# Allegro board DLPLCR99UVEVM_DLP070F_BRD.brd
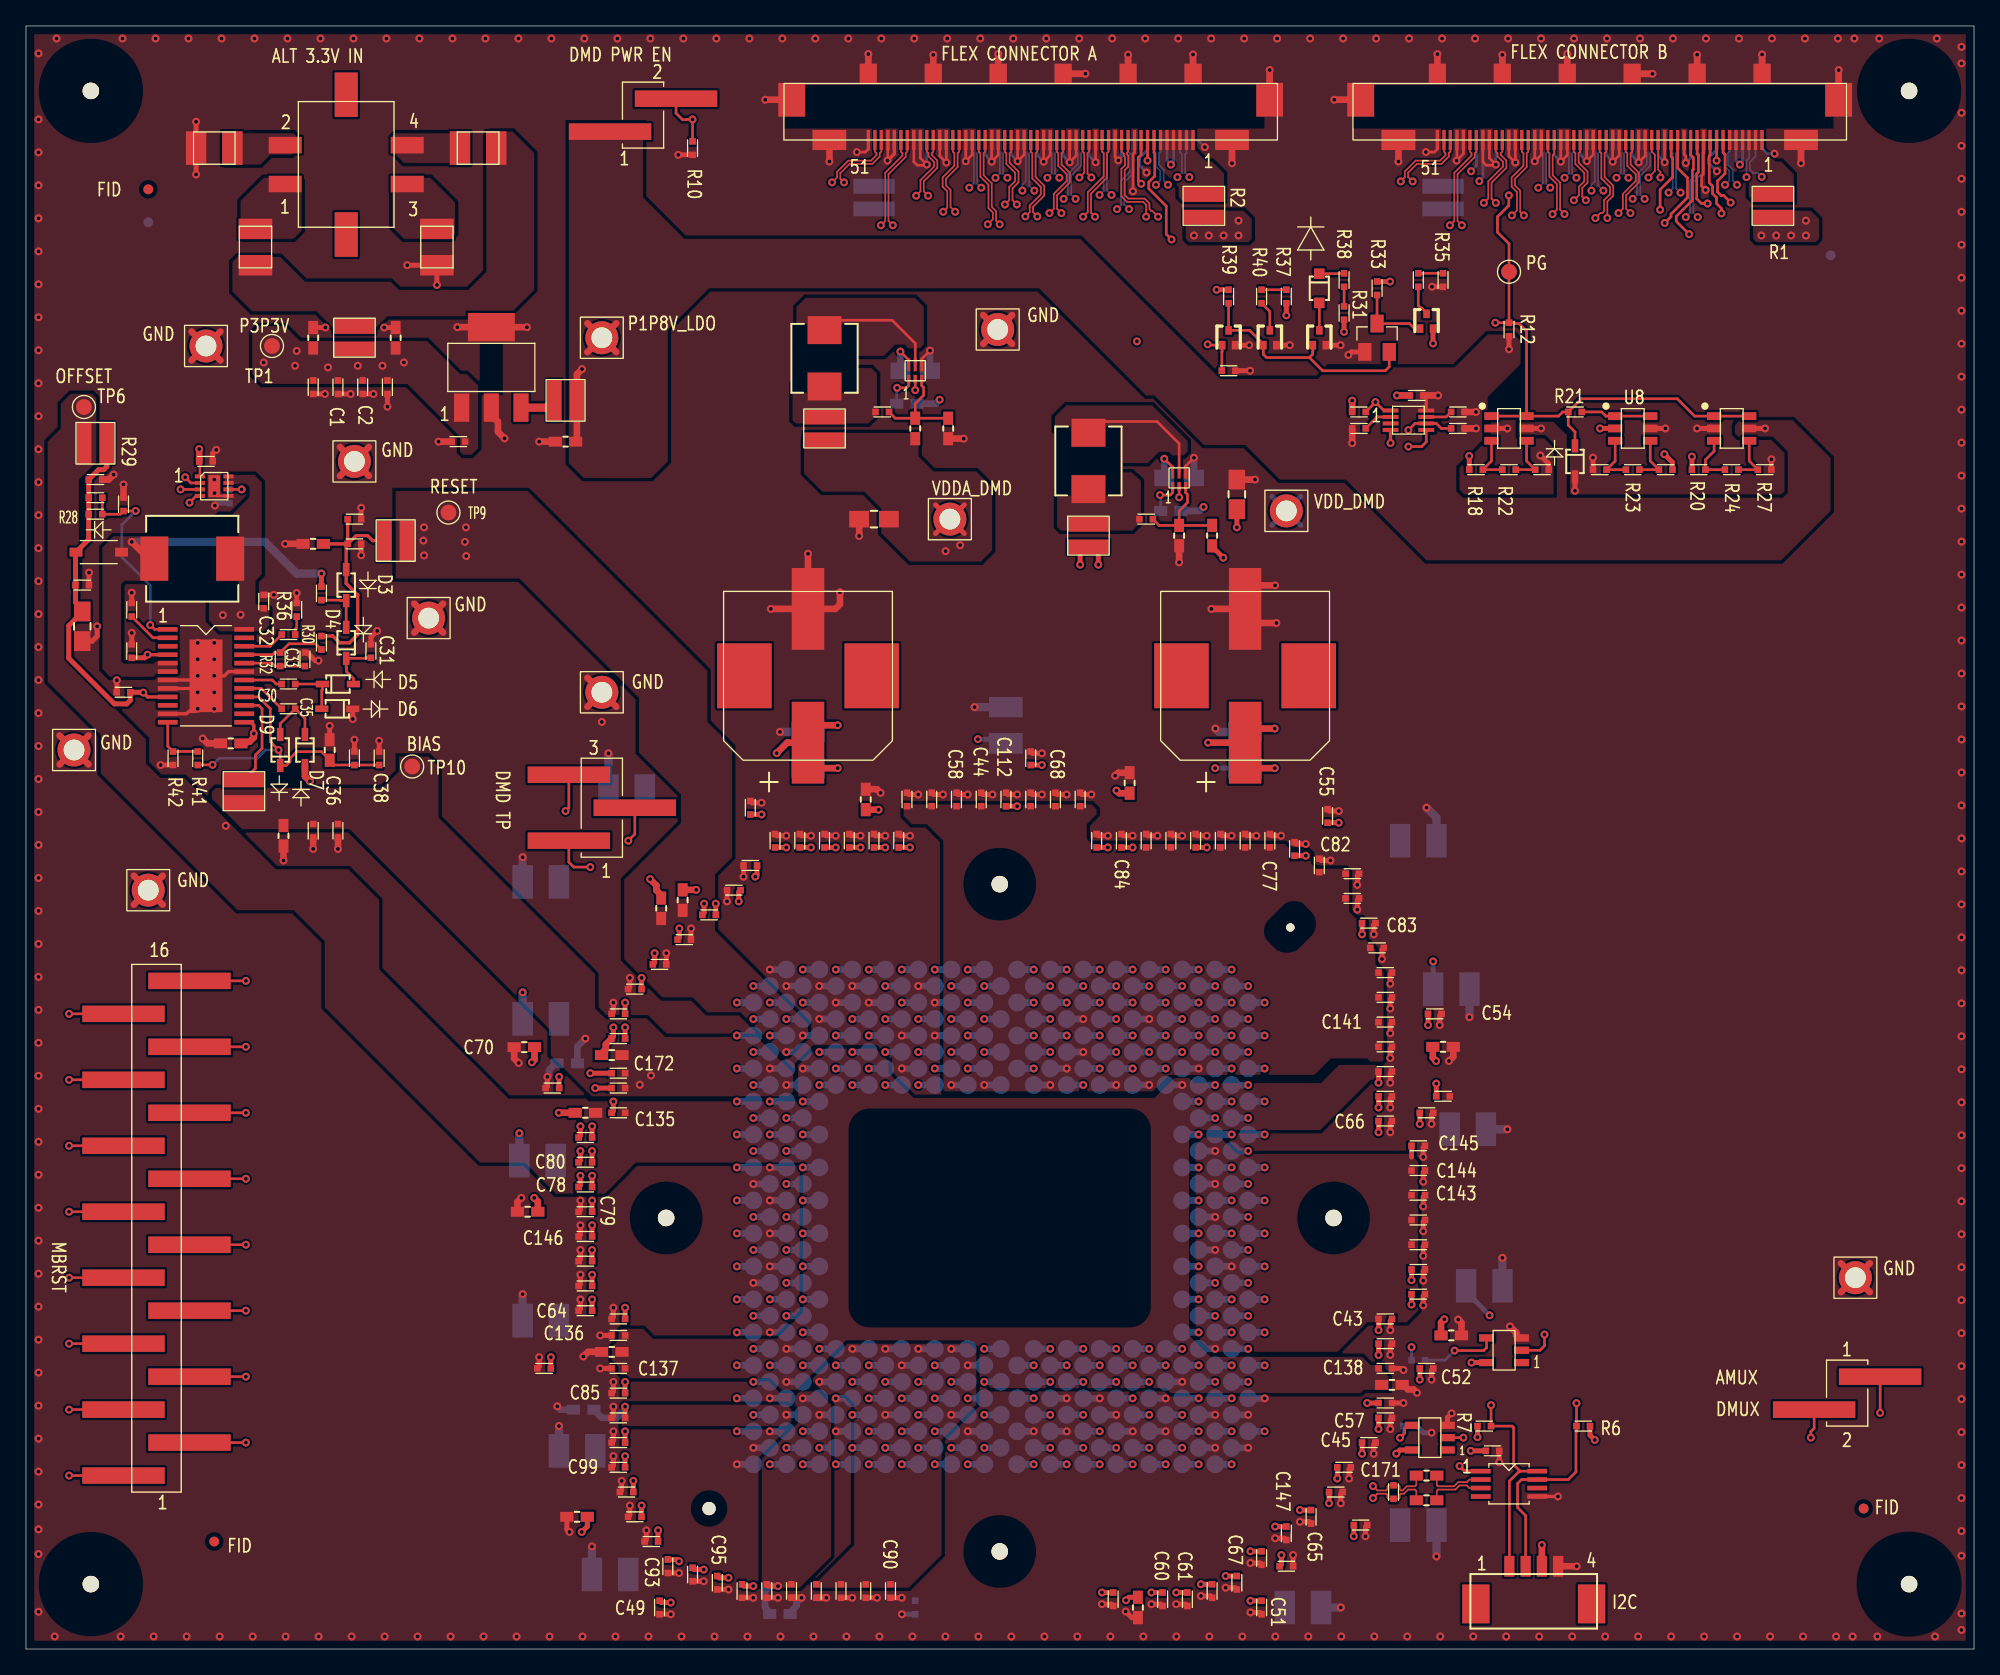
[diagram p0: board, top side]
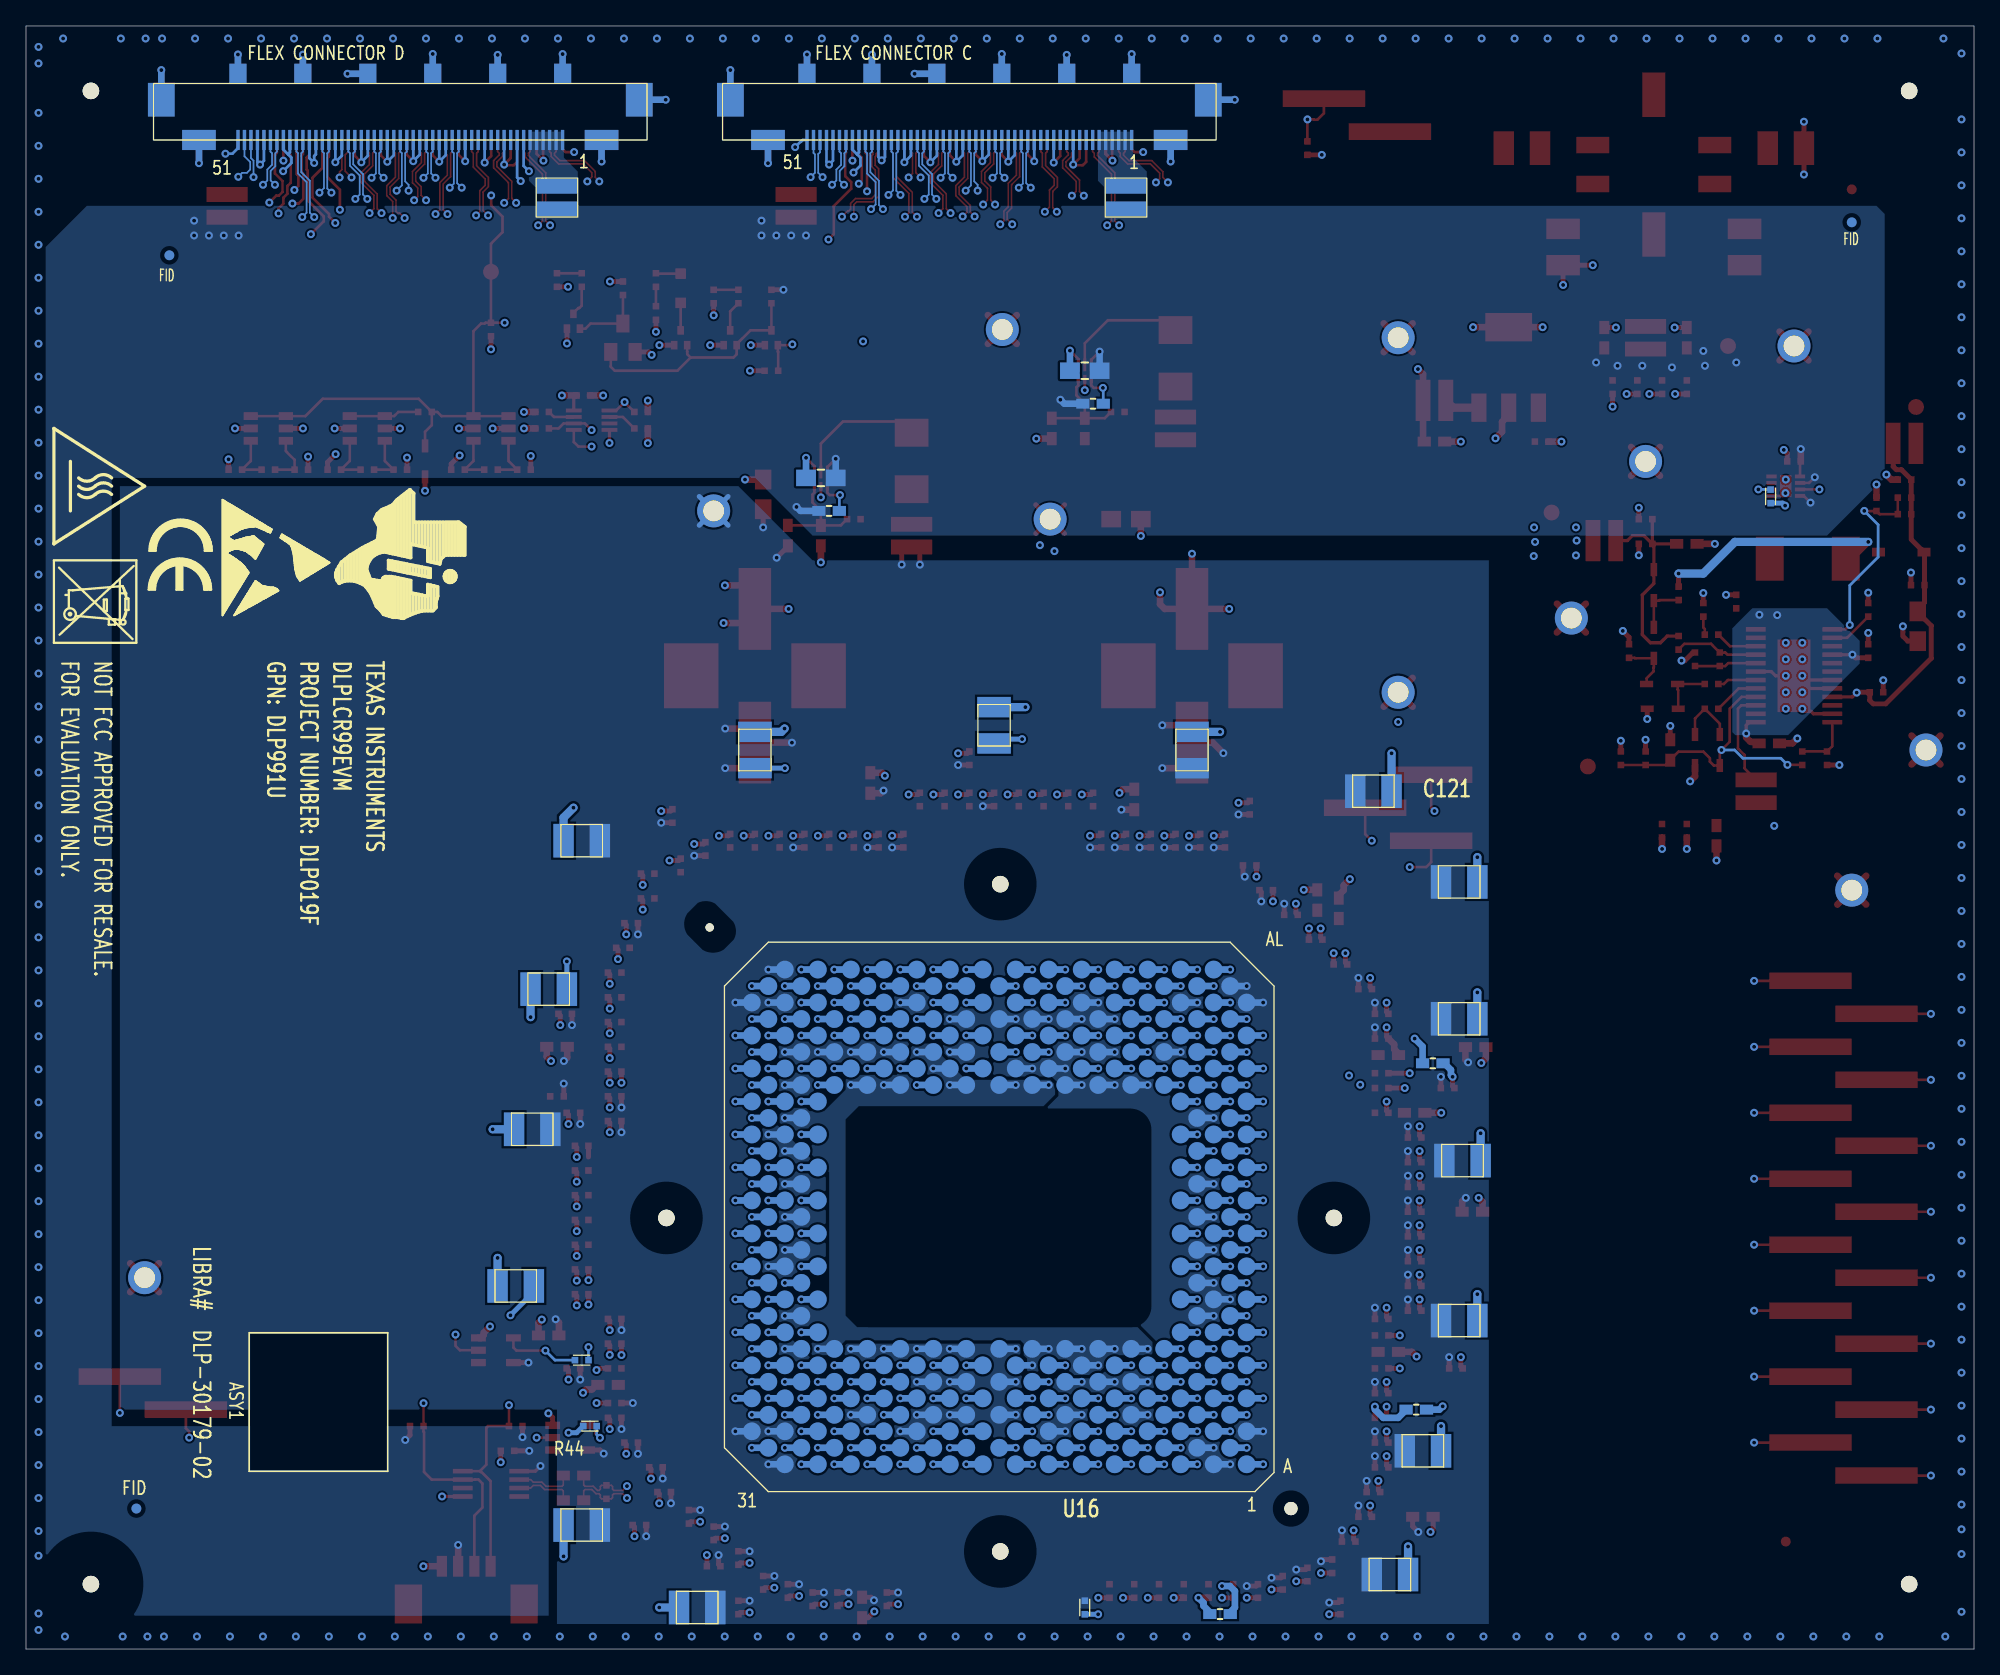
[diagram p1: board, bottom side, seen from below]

Outline 150 x 125 mm; copper layers: TOP, LY2-SIG, LY3-GND, LY4-SIG, LY5-GND, LY6-SIG, LY7-GND, BOTTOM. Coordinates in mm from the lower left corner of the outline.
Outline path: 0,125 150,125 150,0 0,0 0,125

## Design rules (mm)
constraint set DEFAULT: min track width 0.203
net group 100OHM: nets N16806960 N16807032
net group DIFFPAIR1: nets N16806468 N16806470
nets with their own width: min track width 0.381; nets VDD_DMD VDDA_DMD
nets with their own width: min track width 0.508; nets P1P8V_LDO

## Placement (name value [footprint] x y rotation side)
ASY1  -  []  127.52 19.07 180 bottom
C1  1u  [0402]  24.02 97.18 90 top
C2  0.1u  [0402]  25.92 97.18 90 top
C3  10u  [0603]  22.11 100.99 270 top
C4  10u  [0603]  28.46 100.99 270 top
C5  1u  [0402]  22.11 97.18 90 top
C6  0.1u  [0402]  27.83 97.18 90 top
C17  1u  [0402]  13.86 91.46 180 top
C18  4700p  [0402]  15.66 88.77 90 bottom
C19  10u  [0603]  15.76 69.75 0 top
C20  1u  [0402]  8.14 76.86 270 top
C21  0.1u  [0402]  18.3 80.67 270 top
C22  22u  [0805]  4.33 78.76 90 top
C23  1u  [0402]  4.33 81.94 180 top
C24  0.1u  [0402]  7.51 73.68 0 top
C25  47p  [0402]  5.35 88.67 180 top
C26  1u  [0402]  22.75 81.3 90 top
C27  10u  [0603]  22.11 85.11 180 top
C28  1u  [0402]  25.29 85.11 180 top
C29  0.1u  [0402]  25.29 87.02 180 top
C30  1u  [0402]  20.21 74.32 180 top
C31  0.33u  [0402]  26.56 76.86 90 top
C32  470p  [0402]  20.21 78.13 0 top
C33  0.22u  [0402]  21.48 76.22 270 top
C34  8200p  [0402]  8.14 80.03 90 top
C35  1u  [0402]  20.21 72.41 180 top
C36  10u  [0603]  23.38 69.24 90 top
C37  1u  [0402]  25.29 68.6 270 top
C38  0.1u  [0402]  27.19 68.6 270 top
C39  0.1u  [0402]  104.66 50.19 180 top
C40  0.1u  [0402]  97.68 61.62 270 top
C41  0.1u  [0402]  104.66 52.09 180 top
C42  0.1u  [0402]  104.66 18.95 180 top
C43  0.1u  [0402]  104.66 25.42 180 top
C44  0.1u  [0402]  73.55 65.43 270 top
C45  0.1u  [0402]  103.39 15.9 180 top
C46  0.1u  [0402]  68.47 3.2 90 bottom
C47  1u  [0402]  55.77 64.79 270 top
C48  1u  [0402]  45.61 47.01 0 top
C49  1u  [0402]  48.78 3.2 90 top
C50  1u  [0402]  39.89 21.61 0 top
C51  1u  [0402]  95.14 3.2 90 top
C52  1u  [0402]  107.84 21.61 180 top
C53  1u  [0402]  102.76 9.55 180 top
C54  1u  [0402]  108.47 48.92 180 top
C55  1u  [0402]  100.22 64.16 270 top
C56  1u  [0402]  77.36 68.6 270 top
C57  0.1u  [0402]  104.66 17.8 180 top
C58  0.1u  [0402]  71.64 65.43 270 top
C59  0.1u  [0402]  83.71 3.83 90 top
C60  0.1u  [0402]  87.52 3.83 90 top
C61  0.1u  [0402]  89.42 3.83 90 top
C62  0.1u  [0402]  95.14 7.01 90 top
C63  0.1u  [0402]  107.2 33.04 180 top
C64  0.1u  [0402]  43.07 26.06 0 top
C65  0.1u  [0402]  98.95 10.18 90 top
C66  0.1u  [0402]  104.66 40.66 180 top
C67  0.1u  [0402]  93.23 5.1 90 top
C68  0.1u  [0402]  79.26 65.43 270 top
C69  10u  [0603]  64.66 65.43 270 top
C70  10u  [0603]  38.37 46.35 0 top
C71  10u  [0603]  38.62 33.68 0 top
C72  10u  [0603]  42.43 10.18 0 top
C73  10u  [0603]  85.61 3.2 90 top
C74  10u  [0603]  109.74 24.15 180 top
C75  10u  [0603]  109.11 46.38 180 top
C76  10u  [0603]  84.98 66.7 270 top
C77  0.1u  [0402]  95.77 62.25 270 top
C78  0.1u  [0402]  43.07 35.58 0 top
C79  0.1u  [0402]  43.07 33.68 0 top
C80  0.1u  [0402]  43.07 37.49 0 top
C81  0.1u  [0402]  55.13 4.47 90 top
C82  0.1u  [0402]  99.58 60.35 270 top
C83  0.1u  [0402]  103.39 55.9 180 top
C84  0.1u  [0402]  84.34 62.25 270 top
C85  0.1u  [0402]  45.61 19.71 0 top
C86  100u  [1210]  44.97 5.74 0 bottom
C87  100u  [1210]  111.01 40.03 180 bottom
C88  100u  [1210]  39.39 37.62 0 bottom
C89  100u  [1210]  60.21 69.24 270 bottom
C90  0.1u  [0402]  66.56 4.47 90 top
C91  470u  [CAP2-146CTI-1213_VISHAY]  93.87 74.95 270 top
C92  470u  [CAP2-146CTI-1213_VISHAY]  60.21 74.95 270 top
C93  0.1u  [0402]  49.42 6.37 90 top
C94  0.1u  [0402]  62.75 4.47 90 top
C95  0.1u  [0402]  53.23 5.1 90 top
C96  0.1u  [0402]  102.12 57.81 180 top
C97  0.1u  [0402]  107.2 29.23 180 top
C98  0.1u  [0402]  107.2 27.33 180 top
C99  0.1u  [0402]  45.61 13.99 0 top
C100  0.1u  [0402]  43.07 29.87 0 top
C101  0.1u  [0402]  43.07 27.96 0 top
C102  0.1u  [0402]  61.48 62.25 270 top
C103  0.1u  [0402]  63.39 62.25 270 top
C104  0.1u  [0402]  48.15 8.28 0 top
C105  0.1u  [0402]  46.88 10.18 0 top
C106  0.1u  [0402]  69.74 65.43 270 top
C107  0.1u  [0402]  59.58 62.25 270 top
C108  0.1u  [0402]  67.83 65.43 270 top
C109  0.1u  [0402]  67.2 62.25 270 top
C110  0.1u  [0402]  65.29 62.25 270 top
C111  0.1u  [0402]  55.77 60.35 0 top
C112  0.1u  [0402]  75.45 65.43 270 top
C113  100u  [1210]  93.87 69.24 270 bottom
C114  100u  [1210]  107.2 62.25 180 bottom
C115  100u  [1210]  109.74 50.82 180 bottom
C116  100u  [1210]  107.2 9.55 180 bottom
C117  100u  [1210]  98.31 3.2 180 bottom
C118  100u  [1210]  39.64 48.54 0 bottom
C119  100u  [1210]  42.43 15.26 0 bottom
C120  100u  [1210]  39.64 59.08 0 bottom
C121  100u  [1210]  46.24 66.06 0 bottom
C122  100u  [1210]  39.64 25.3 0 bottom
C123  100u  [1210]  75.45 71.14 270 bottom
C124  100u  [1210]  112.28 27.96 180 bottom
C125  0.1u  [0402]  107.2 31.14 180 top
C126  0.1u  [0402]  52.59 56.54 0 top
C127  0.1u  [0402]  54.5 58.44 0 top
C128  0.1u  [0402]  60.85 4.47 90 top
C129  0.1u  [0402]  91.33 4.47 90 top
C130  0.1u  [0402]  104.66 42.57 180 top
C131  0.1u  [0402]  40.53 43.2 0 top
C132  0.1u  [0402]  45.61 48.92 0 top
C133  0.1u  [0402]  43.07 39.39 0 top
C134  0.1u  [0402]  46.88 50.82 0 top
C135  0.1u  [0402]  45.61 41.3 0 top
C136  0.1u  [0402]  45.61 24.15 0 top
C137  0.1u  [0402]  45.61 21.61 0 top
C138  0.1u  [0402]  104.66 21.61 180 top
C139  0.1u  [0402]  104.66 44.47 180 top
C140  0.1u  [0402]  86.25 62.25 270 top
C141  0.1u  [0402]  104.66 48.28 180 top
C142  0.1u  [0402]  81.17 65.43 270 top
C143  0.1u  [0402]  107.2 34.95 180 top
C144  0.1u  [0402]  107.2 36.85 180 top
C145  0.1u  [0402]  107.2 38.76 180 top
C146  0.1u  [0402]  43.07 31.77 0 top
C147  0.1u  [0402]  97.04 8.91 90 top
C148  0.1u  [0402]  104.66 23.52 180 top
C149  0.1u  [0402]  64.66 4.47 90 top
C150  0.1u  [0402]  45.61 25.42 0 top
C151  0.1u  [0402]  100.85 12.09 180 top
C152  0.1u  [0402]  107.84 41.3 180 top
C153  0.1u  [0402]  57.67 62.25 270 top
C154  0.1u  [0402]  51.32 5.74 90 top
C155  0.1u  [0402]  102.12 59.71 180 top
C156  0.1u  [0402]  97.04 6.37 180 top
C157  0.1u  [0402]  45.61 15.9 0 top
C158  0.1u  [0402]  77.36 65.43 270 top
C159  0.1u  [0402]  104.66 46.38 180 top
C160  0.1u  [0402]  57.04 4.47 90 top
C161  0.1u  [0402]  58.94 4.47 90 top
C162  0.1u  [0402]  50.69 54.63 0 top
C163  0.1u  [0402]  48.78 52.73 0 top
C164  0.1u  [0402]  46.24 12.09 0 top
C165  0.1u  [0402]  91.96 62.25 270 top
C166  0.1u  [0402]  82.44 62.25 270 top
C167  0.1u  [0402]  90.06 62.25 270 top
C168  0.1u  [0402]  104.03 54 180 top
C169  0.1u  [0402]  93.87 62.25 270 top
C170  0.1u  [0402]  88.15 62.25 270 top
C171  0.1u  [0402]  101.49 13.99 180 top
C172  0.1u  [0402]  45.61 44.35 0 top
C173  0.1u  [0402]  45.61 43.2 0 top
C174  0.1u  [0402]  45.61 17.8 0 top
C175  0.1u  [0402]  112.92 15.26 180 top
C176  180p  [0402]  105.3 12.09 90 top
C177  2.2u  [0402]  5.35 90.07 180 top
C179  0.1u  [0402]  107.08 96.54 0 top
C181  10u  [0603]  41.55 92.99 0 top
C182  10u  [0603]  43.07 41.3 0 top
C183  10u  [0603]  45.1 22.88 0 top
C184  10u  [0603]  105.17 20.34 180 top
C185  10u  [0603]  48.91 57.05 270 top
C186  10u  [0603]  50.56 57.68 270 top
C187  10u  [0603]  58.06 2.69 180 bottom
C188  10u  [0603]  45.1 45.74 0 top
C189  10u  [0603]  41.67 45.11 0 bottom
C190  10u  [0603]  42.94 18.44 0 bottom
C191  10u  [0603]  19.83 62.64 270 top
C192  1u  [0402]  24.02 63.02 90 top
C193  0.1u  [0402]  22.11 63.02 90 top
C194  120 pF  [0402]  86.25 87.02 180 top
C195  4.7 uF  [0805]  88.79 90.19 180 bottom
C196  33u  [0805]  93.23 88.92 270 top
C197  4.7 uF  [0805]  68.47 98.45 180 bottom
C198  120 pF  [0402]  65.93 95.27 180 top
C199  33u  [0805]  65.29 87.02 0 top
C200  0.1u  [0402]  109.11 42.57 180 top
C201  1u  [0402]  33.29 92.99 0 top
D1  PMEG3010  [SOD323-REV_MCC]  119.27 91.46 270 top
D2  CDBW0540  [SOD-123-STP-REV_ST]  5.6 84.48 180 top
D3  PMEG3010  [SOD323-REV_MCC]  24.65 81.94 90 top
D4  PMEG3010  [SOD323-REV_MCC]  24.65 77.49 90 top
D5  PMEG3010  [SOD323-REV_MCC]  24.02 74.32 0 top
D6  PMEG3010  [SOD323-REV_MCC]  23.97 72.41 180 top
D7  PMEG3010  [SOD323-REV_MCC]  21.48 69.24 270 top
D8  3.3V  [DIO-SOD323F_FC]  99.58 104.8 270 top
D9  PMEG3010  [SOD323-REV_MCC]  19.57 69.24 90 top
FB1  FB  [1210]  34.81 115.59 180 top
FB2  FB  [1210]  17.67 107.97 90 top
FB3  FB  [1210]  31.64 107.97 90 top
FB4  FB  [1210]  14.49 115.59 0 top
FID  -  [unnamed#2]  141.49 10.82 0 top
FID#2  -  [unnamed#2]  9.41 112.42 0 top
FID#3  -  [unnamed#2]  14.49 8.28 0 top
FID#4  -  [unnamed#2]  141.49 10.82 180 bottom
FID#5  -  [unnamed#2]  9.41 109.88 180 bottom
FID#6  -  [unnamed#2]  138.95 107.34 180 bottom
J1  FI-RE51S-HF-R1500  [CONN51-FI-R_JAE]  77.36 118.77 180 top
J2  FI-RE51S-HF-R1500  [CONN51-FI-R_JAE]  121.17 118.77 180 top
J3  FI-RE51S-HF-R1500  [CONN51-FI-R_JAE]  77.36 118.77 0 bottom
J4  FI-RE51S-HF-R1500  [CONN51-FI-R_JAE]  121.17 118.77 0 bottom
J5  0532610471  [CONN4-53261-A_MOLEX]  116.09 6.37 0 top
J6  GBC02SABN-M30  [CONN2-GBC02SABN-M30_SUL]  47.51 118.13 0 top
J7  Molex 43045-0420  [CONN4-43045-0418_MLX]  24.65 114.32 90 top
J8  GBC02SABN-M30  [CONN2-GBC02SABN-M30_SUL]  140.22 19.71 180 top
J9  GBC16SABN-M30  [CONN16-GBC16SABN-M30_SUL]  10.05 32.41 0 top
J10  GBC03SABN-M30  [CONN3-GBC03SABN-M30_SUL]  44.34 64.79 0 top
L2  2.2uH  [IND_SRP7028C]  12.8 83.97 180 top
L3  470 nH  [IND_SPM5030VT]  81.8 91.5 270 top
L4  470 nH  [IND_SPM5030VT]  61.48 99.41 270 top
NOREF  -  []  52.59 10.82 0 top
NOREF#2  -  [unnamed#3]  100.68 33.2 157.5 top
NOREF#3  -  []  -16.9 -14.58 180 top
NOREF#4  -  []  85.97 26.41 0 top
NOREF#5  -  [unnamed#3]  49.29 33.2 157.5 top
NOREF#6  -  [unnamed#3]  74.97 58.91 157.5 top
NOREF#7  -  [unnamed#3]  5 120 0 top
NOREF#8  -  []  213.49 74.66 0 top
NOREF#9  -  []  0 0 0 top
NOREF#10  -  []  0.5 -65.46 0 top
NOREF#11  -  []  84.97 25.41 0 top
NOREF#12  -  []  52.59 10.82 0 top
NOREF#13  -  [unnamed#3]  144.99 120 0 top
NOREF#14  -  [unnamed#3]  5 5 0 top
NOREF#15  -  []  0 125 0 top
NOREF#16  -  []  63.97 39.99 0 top
NOREF#17  -  []  0 0 0 top
NOREF#18  -  []  160.9 137.82 180 top
NOREF#19  -  [unnamed#3]  74.97 7.52 157.5 top
NOREF#20  -  []  9.25 87.27 0 top
NOREF#21  -  []  58.93 96.76 0 top
NOREF#22  -  []  9.25 80.67 90 top
NOREF#23  -  [unnamed#3]  97.36 55.57 135 top
NOREF#24  -  []  58.78 12.05 0 top
NOREF#25  -  [unnamed#3]  52.59 10.82 157.5 top
NOREF#26  -  []  -16.9 137.82 180 top
NOREF#27  -  []  79.25 88.85 90 top
NOREF#28  -  []  150 0 90 top
NOREF#29  -  []  150 0 0 top
NOREF#30  -  []  79.25 88.85 0 top
NOREF#31  -  []  58.93 96.76 90 top
NOREF#32  -  []  0 125 0 top
NOREF#33  -  [unnamed#3]  144.99 5 0 top
NOREF#34  -  []  84.97 40.99 0 top
NOREF#35  -  []  140.22 87.65 270 bottom
NOREF#36  -  []  131.33 83.84 270 bottom
NOREF#37  -  []  147.84 83.84 270 bottom
NOREF#38  -  []  121.17 83.84 270 bottom
NOREF#39  -  []  147.84 94 270 bottom
R1  10m  [1206-WIDE-LTR18_ROHM]  134.51 111.15 270 top
R2  10m  [1206-WIDE-LTR18_ROHM]  90.69 111.15 270 top
R3  10m  [1206-WIDE-LTR18_ROHM]  65.29 111.78 270 bottom
R4  10m  [1206-WIDE-LTR18_ROHM]  109.11 111.78 270 bottom
R6  2.2k  [0402]  119.9 17.17 0 top
R7  2.2k  [0402]  112.28 17.17 180 top
R9  10m  [1206-WIDE-LTR18_ROHM]  25.29 100.99 270 top
R10  10k  [0402]  51.32 115.59 90 top
R12  2.2k  [0402]  114.19 101.62 270 top
R18  1.8MEG  [0402]  111.65 90.83 180 top
R19  2.7MEG  [0402]  121.17 90.83 180 top
R20  3.3MEG  [0402]  128.79 90.83 180 top
R21  9.1k  [0402]  119.27 95.27 180 top
R22  6.2k  [0402]  114.19 90.83 180 top
R23  4.53k  [0402]  123.71 90.83 180 top
R24  3k  [0402]  131.33 90.83 180 top
R25  71.5k  [0402]  116.73 90.83 180 top
R26  76.8k  [0402]  126.25 90.83 180 top
R27  73.2k  [0402]  133.87 90.83 180 top
R28  499k  [0402]  5.35 87.4 180 top
R29  63.4k  [0402]  7.51 88.16 270 top
R30  576k  [0402]  22.75 77.49 90 top
R31  12  [0402]  101.49 102.89 270 top
R32  49.9k  [0402]  19.57 76.22 90 top
R33  2.2k  [0402]  104.03 104.8 90 top
R34  12  [0402]  107.2 105.43 270 top
R35  12  [0402]  109.11 105.43 90 top
R36  56.0K  [0402]  20.84 80.03 90 top
R37  12  [0402]  97.04 104.16 270 top
R38  12  [0402]  101.49 105.43 270 top
R39  1k  [0402]  92.6 104.16 90 top
R40  12  [0402]  95.14 104.16 90 top
R41  649k  [0402]  13.22 68.6 270 top
R42  47k  [0402]  11.32 68.6 90 top
R43  4.7k  [0402]  92.6 98.45 180 top
R44  10k  [0402]  106.57 17.17 180 bottom
R45  0  [0402]  107.2 22.25 0 bottom
R46  51  [0603]  107.84 13.36 0 top
R47  51  [0603]  107.84 11.45 0 top
R48  10m  [1206-WIDE-LTR18_ROHM]  5.35 92.86 180 top
R49  10m  [1206-WIDE-LTR18_ROHM]  28.46 85.37 0 top
R50  10m  [1206-WIDE-LTR18_ROHM]  16.78 66.06 90 top
R53  10k  [0402]  102.63 94 180 top
R54  10k  [0402]  110.25 95.27 0 top
R55  10m  [1206-WIDE-LTR18_ROHM]  41.55 96.16 0 top
R56  10k  [0402]  110.25 94 0 top
R57  10k  [0402]  102.63 95.27 0 top
R58  330k  [0603]  91.33 85.75 270 top
R59  100k  [0603]  88.79 85.75 90 top
R60  100k  [0603]  88.15 87.65 0 bottom
R61  10m  [1206-WIDE-LTR18_ROHM]  81.8 85.75 270 top
R62  10m  [1206-WIDE-LTR18_ROHM]  61.48 94 270 top
R63  100k  [0603]  67.83 95.91 0 bottom
R64  330k  [0603]  68.47 94 270 top
R65  100k  [0603]  71.01 94 90 top
TP1  Testpoint  [TP-48RD]  18.94 100.35 0 top
TP2  GND Testpoint  [TP-5006-GND_KEY]  13.86 100.35 0 top
TP4  GND Testpoint  [TP-5006-GND_KEY]  74.82 101.62 0 top
TP5  Testpoint  [TP-48RD]  114.19 106.07 0 top
TP6  Testpoint  [TP-48RD]  4.46 95.66 0 top
TP7  GND Testpoint  [TP-5006-GND_KEY]  3.7 69.24 0 top
TP8  GND Testpoint  [TP-5006-GND_KEY]  25.29 91.46 0 top
TP9  Testpoint  [TP-48RD]  32.53 87.53 0 top
TP10  Testpoint  [TP-48RD]  29.73 67.97 0 top
TP11  GND Testpoint  [TP-5006-GND_KEY]  31 79.4 0 top
TP12  GND Testpoint  [TP-5006-GND_KEY]  140.86 28.6 0 top
TP13  GND Testpoint  [TP-5006-GND_KEY]  9.41 58.44 0 top
TP14  GND Testpoint  [TP-5006-GND_KEY]  44.34 73.68 0 top
TP15  GND Testpoint  [TP-5006-GND_KEY]  97.04 87.65 0 top
TP16  GND Testpoint  [TP-5006-GND_KEY]  71.14 87.02 0 top
TP17  GND Testpoint  [TP-5006-GND_KEY]  44.34 100.99 0 top
U6  TPS22975  [SOIC8-DSG_TI]  14.49 89.56 0 top
U7  TPS3700  [SOIC6-DDC_TI]  114.19 94 0 top
U8  TPS3700  [SOIC6-DDC_TI]  123.71 94 0 top
U9  TPS3700  [SOIC6-DDC_TI]  131.33 94 0 top
U10  TPS65150  [SOIC24-PWP_TI_A]  13.86 74.95 270 top
U11  SI1012X  [SOT-490-SC89-3_FC]  107.84 102.26 0 top
U12  SI1012X  [SOT-490-SC89-3_FC]  92.6 100.99 0 top
U13  SI1012X  [SOT-490-SC89-3_FC]  95.77 100.99 0 top
U14  SI1012X  [SOT-490-SC89-3_FC]  99.58 100.99 0 top
U15  BSS84  [SOT23-3_FC]  104.03 100.99 180 top
U16  2515700 (Interposer)  [DMD-98-DC4K-TRP-FLRA_TI]  56 14.23 0 bottom
U17  ADT7461  [SOIC8-DGK_TI]  114.19 12.72 270 top
U18  SN74AUC1G74  [SOIC8-DCU_TI]  106.44 94.64 270 top
U19  TLV117118DCYR  [SOT223AVX]  35.83 98.7 0 top
U22  SN74LVC1G17  [SOIC5-SOT-23_DBV-TI]  113.81 23.01 90 top
U23  SN74LVC1G17  [SOIC5-SOT-23_DBV-TI]  108.09 16.28 90 top
U24  TPS62827DMQ  [SOIC6-VSON-HR-DMQ_TI]  88.79 90.19 90 top
U25  TPS62827DMQ  [SOIC6-VSON-HR-DMQ_TI]  68.47 98.45 90 top

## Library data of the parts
C1-C6 C17-C85 C90 C93-C112 C125-C177 C179 C181-C201 = C
C86-C89 C113-C124 = C: Tolerance: TOL
C91 C92 = CAPACITOR_POL
D1-D7 D9 = DIODE_SCHOTTKY_dsize
D8 = DIODE ZENER
FB1-FB4 = Ferrite Bead_1: Tolerance: TOL
J1-J4 = FI-RE51S-VF-R1300
J5 = Conn_4
J6 J8 = 2x1 Header
J7 = Molex 43045-0418_0
J9 = 16x1 Header
J10 = 3x1 Header
L2-L4 = L
R1-R4 R6 R7 R9 R10 R12 R18-R50 R53-R65 = R
TP1 TP2 TP4-TP17 = Testpoint
U6 = TPS22967_4
U7-U9 = TPS3700
U10 = TPS65150_2
U11-U14 = FDV303N
U15 = BSS84
U16 = DLP990U_DMD_SOCKET
U17 = TMP411
U18 = SN74AUC1G74
U19 = TLV117118DCYR
U22 U23 = SN74LVC1G06
U24 U25 = TPS62827DMQ

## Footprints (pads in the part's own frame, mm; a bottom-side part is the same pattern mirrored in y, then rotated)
0402
  rect 0.508x0.508 smd: 1(-0.521,0) 2(0.521,0)
0603
  rect 1.016x0.762 smd: 1(-0.787,0) 2(0.787,0)
0805
  rect 1.524x1.27 smd: 1(-1.143,0) 2(1.143,0)
1206-WIDE-LTR18_ROHM
  rect 1.143x3.175 smd: 1(-0.875,0) 2(0.875,0)
1210
  rect 1.575x2.591 smd: 1(-1.397,0) 2(1.397,0)
CAP2-146CTI-1213_VISHAY
  rect 5x4.2 smd: (0,4.9) (0,-4.9)
  rect 6.3x2.5 smd: 1(5.15,0) 2(-5.15,0)
CONN2-GBC02SABN-M30_SUL
  rect 6.35x1.27 smd: 1(-2.54,-1.27) 2(2.54,1.27)
CONN3-GBC03SABN-M30_SUL
  rect 6.35x1.27 smd: 1(-2.54,-2.54) 2(2.54,0) 3(-2.54,2.54)
CONN4-43045-0418_MLX
  rect 3.429x1.778 smd: (-5.385,0) (5.385,0)
  rect 1.27x2.54 smd: 1(-1.499,4.699) 2(1.499,4.699) 3(-1.499,-4.699) 4(1.499,-4.699)
CONN4-53261-A_MOLEX
  rect 2.108x2.997 smd: (-4.455,-2.9) (4.455,-2.9)
  rect 0.787x1.6 smd: 1(-1.875,0) 2(-0.625,0) 3(0.625,0) 4(1.875,0)
CONN16-GBC16SABN-M30_SUL
  rect 6.35x1.27 smd: 1(-2.54,-19.05) 2(2.54,-16.51) 3(-2.54,-13.97) 4(2.54,-11.43) 5(-2.54,-8.89) 6(2.54,-6.35) 7(-2.54,-3.81) 8(2.54,-1.27) 9(-2.54,1.27) 10(2.54,3.81) 11(-2.54,6.35) 12(2.54,8.89) 13(-2.54,11.43) 14(2.54,13.97) 15(-2.54,16.51) 16(2.54,19.05)
CONN51-FI-R_JAE
  rect 0.254x1.549 smd: 1(-12.497,2.55) 2(-11.997,2.55) 3(-11.497,2.55) 4(-10.997,2.55) 5(-10.497,2.55) 6(-9.997,2.55) 7(-9.498,2.55) 8(-8.998,2.55) 9(-8.498,2.55) 10(-7.998,2.55) 11(-7.498,2.55) 12(-6.998,2.55) 13(-6.498,2.55) 14(-5.998,2.55) 15(-5.499,2.55) 16(-4.999,2.55) 17(-4.499,2.55) 18(-3.999,2.55) 19(-3.499,2.55) 20(-2.999,2.55) 21(-2.499,2.55) 22(-1.999,2.55) 23(-1.5,2.55) 24(-1,2.55) 25(-0.5,2.55) 26(0,2.55) 27(0.5,2.55) 28(1,2.55) 29(1.5,2.55) 30(1.999,2.55) 31(2.499,2.55) 32(2.999,2.55) 33(3.499,2.55) 34(3.999,2.55) 35(4.499,2.55) 36(4.999,2.55) 37(5.499,2.55) 38(5.998,2.55) 39(6.498,2.55) 40(6.998,2.55) 41(7.498,2.55) 42(7.998,2.55) 43(8.498,2.55) 44(8.998,2.55) 45(9.498,2.55) 46(9.997,2.55) 47(10.497,2.55) 48(10.997,2.55) 49(11.497,2.55) 50(11.997,2.55) 51(12.497,2.55)
  rect 2.591x1.549 smd: 52(15.5,2.55) 61(-15.5,2.55)
  rect 2.057x2.591 smd: 53(18.4,-0.55) 60(-18.4,-0.55)
  rect 1.321x1.549 smd: 54(12.5,-2.55) 55(7.5,-2.55) 56(2.5,-2.55) 57(-2.5,-2.55) 58(-7.5,-2.55) 59(-12.5,-2.55)
DIO-SOD323F_FC
  rect 0.813x0.813 smd: 1(-1.125,0) 2(1.125,0)
DMD-98-DC4K-TRP-FLRA_TI
  round 1.372 smd: A1(0,0) A3(2.54,0) A5(5.08,0) A7(7.62,0) A9(10.16,0) A11(12.7,0) A13(15.24,0) A15(17.78,0) A17(20.32,0) A19(22.86,0) A21(25.4,0) A23(27.94,0) A25(30.48,0) A27(33.02,0) A29(35.56,0) AA1(0,-25.4) AA3(2.54,-25.4) AA5(5.08,-25.4) AA27(33.02,-25.4) AA29(35.56,-25.4) AA31(38.1,-25.4) AB2(1.27,-26.67) AB4(3.81,-26.67) AB28(34.29,-26.67) AB30(36.83,-26.67) AC1(0,-27.94) AC3(2.54,-27.94) AC5(5.08,-27.94) AC27(33.02,-27.94) AC29(35.56,-27.94) AC31(38.1,-27.94) AD2(1.27,-29.21) AD4(3.81,-29.21) AD6(6.35,-29.21) AD8(8.89,-29.21) AD10(11.43,-29.21) AD12(13.97,-29.21) AD14(16.51,-29.21) AD16(19.05,-29.21) AD18(21.59,-29.21) AD20(24.13,-29.21) AD22(26.67,-29.21) AD24(29.21,-29.21) AD26(31.75,-29.21) AD28(34.29,-29.21) AD30(36.83,-29.21) AE1(0,-30.48) AE3(2.54,-30.48) AE5(5.08,-30.48) AE7(7.62,-30.48) AE9(10.16,-30.48) AE11(12.7,-30.48) AE13(15.24,-30.48) AE15(17.78,-30.48) AE17(20.32,-30.48) AE19(22.86,-30.48) AE21(25.4,-30.48) AE23(27.94,-30.48) AE25(30.48,-30.48) AE27(33.02,-30.48) AE29(35.56,-30.48) AE31(38.1,-30.48) AF2(1.27,-31.75) AF4(3.81,-31.75) AF6(6.35,-31.75) AF8(8.89,-31.75) AF10(11.43,-31.75) AF12(13.97,-31.75) AF14(16.51,-31.75) AF16(19.05,-31.75) AF18(21.59,-31.75) AF20(24.13,-31.75) AF22(26.67,-31.75) AF24(29.21,-31.75) AF26(31.75,-31.75) AF28(34.29,-31.75) AF30(36.83,-31.75) AG1(0,-33.02) AG3(2.54,-33.02) AG5(5.08,-33.02) AG7(7.62,-33.02) AG9(10.16,-33.02) AG11(12.7,-33.02) AG13(15.24,-33.02) AG15(17.78,-33.02) AG17(20.32,-33.02) AG19(22.86,-33.02) AG21(25.4,-33.02) AG23(27.94,-33.02) AG25(30.48,-33.02) AG27(33.02,-33.02) AG29(35.56,-33.02) AG31(38.1,-33.02) AH2(1.27,-34.29) AH4(3.81,-34.29) AH6(6.35,-34.29) AH8(8.89,-34.29) AH10(11.43,-34.29) AH12(13.97,-34.29) AH14(16.51,-34.29) AH16(19.05,-34.29) AH18(21.59,-34.29) AH20(24.13,-34.29) AH22(26.67,-34.29) AH24(29.21,-34.29) AH26(31.75,-34.29) AH28(34.29,-34.29) AH30(36.83,-34.29) AJ1(0,-35.56) AJ3(2.54,-35.56) AJ5(5.08,-35.56) AJ7(7.62,-35.56) AJ9(10.16,-35.56) AJ11(12.7,-35.56) AJ13(15.24,-35.56) AJ15(17.78,-35.56) AJ17(20.32,-35.56) AJ19(22.86,-35.56) AJ21(25.4,-35.56) AJ23(27.94,-35.56) AJ25(30.48,-35.56) AJ27(33.02,-35.56) AJ29(35.56,-35.56) AJ31(38.1,-35.56) AK2(1.27,-36.83) AK4(3.81,-36.83) AK6(6.35,-36.83) AK8(8.89,-36.83) AK10(11.43,-36.83) AK12(13.97,-36.83) AK14(16.51,-36.83) AK16(19.05,-36.83) AK18(21.59,-36.83) AK20(24.13,-36.83) AK22(26.67,-36.83) AK24(29.21,-36.83) AK26(31.75,-36.83) AK28(34.29,-36.83) AK30(36.83,-36.83) AL3(2.54,-38.1) AL5(5.08,-38.1) AL7(7.62,-38.1) AL9(10.16,-38.1) AL11(12.7,-38.1) AL13(15.24,-38.1) AL15(17.78,-38.1) AL17(20.32,-38.1) AL19(22.86,-38.1) AL21(25.4,-38.1) AL23(27.94,-38.1) AL25(30.48,-38.1) AL27(33.02,-38.1) AL29(35.56,-38.1) B2(1.27,-1.27) B4(3.81,-1.27) B6(6.35,-1.27) B8(8.89,-1.27) B10(11.43,-1.27) B12(13.97,-1.27) B14(16.51,-1.27) B16(19.05,-1.27) B18(21.59,-1.27) B20(24.13,-1.27) B22(26.67,-1.27) B24(29.21,-1.27) B26(31.75,-1.27) B28(34.29,-1.27) B30(36.83,-1.27) C1(0,-2.54) C3(2.54,-2.54) C5(5.08,-2.54) C7(7.62,-2.54) C9(10.16,-2.54) C11(12.7,-2.54) C13(15.24,-2.54) C15(17.78,-2.54) C17(20.32,-2.54) C19(22.86,-2.54) C21(25.4,-2.54) C23(27.94,-2.54) C25(30.48,-2.54) C27(33.02,-2.54) C29(35.56,-2.54) C31(38.1,-2.54) D2(1.27,-3.81) D4(3.81,-3.81) D6(6.35,-3.81) D8(8.89,-3.81) D10(11.43,-3.81) D12(13.97,-3.81) D14(16.51,-3.81) D16(19.05,-3.81) D18(21.59,-3.81) D20(24.13,-3.81) D22(26.67,-3.81) D24(29.21,-3.81) D26(31.75,-3.81) D28(34.29,-3.81) D30(36.83,-3.81) E1(0,-5.08) E3(2.54,-5.08) E5(5.08,-5.08) E7(7.62,-5.08) E9(10.16,-5.08) E11(12.7,-5.08) E13(15.24,-5.08) E15(17.78,-5.08) E17(20.32,-5.08) E19(22.86,-5.08) E21(25.4,-5.08) E23(27.94,-5.08) E25(30.48,-5.08) E27(33.02,-5.08) E29(35.56,-5.08) E31(38.1,-5.08) F2(1.27,-6.35) F4(3.81,-6.35) F6(6.35,-6.35) F8(8.89,-6.35) F10(11.43,-6.35) F12(13.97,-6.35) F14(16.51,-6.35) F16(19.05,-6.35) F18(21.59,-6.35) F20(24.13,-6.35) F22(26.67,-6.35) F24(29.21,-6.35) F26(31.75,-6.35) F28(34.29,-6.35) F30(36.83,-6.35) G1(0,-7.62) G3(2.54,-7.62) G5(5.08,-7.62) G7(7.62,-7.62) G9(10.16,-7.62) G11(12.7,-7.62) G13(15.24,-7.62) G15(17.78,-7.62) G17(20.32,-7.62) G19(22.86,-7.62) G21(25.4,-7.62) G23(27.94,-7.62) G25(30.48,-7.62) G27(33.02,-7.62) G29(35.56,-7.62) G31(38.1,-7.62) H2(1.27,-8.89) H4(3.81,-8.89) H6(6.35,-8.89) H8(8.89,-8.89) H10(11.43,-8.89) H12(13.97,-8.89) H14(16.51,-8.89) H16(19.05,-8.89) H18(21.59,-8.89) H20(24.13,-8.89) H22(26.67,-8.89) H24(29.21,-8.89) H26(31.75,-8.89) H28(34.29,-8.89) H30(36.83,-8.89) J1(0,-10.16) J3(2.54,-10.16) J5(5.08,-10.16) J27(33.02,-10.16) J29(35.56,-10.16) J31(38.1,-10.16) K2(1.27,-11.43) K4(3.81,-11.43) K28(34.29,-11.43) K30(36.83,-11.43) L1(0,-12.7) L3(2.54,-12.7) L5(5.08,-12.7) L27(33.02,-12.7) L29(35.56,-12.7) L31(38.1,-12.7) M2(1.27,-13.97) M4(3.81,-13.97) M28(34.29,-13.97) M30(36.83,-13.97) N1(0,-15.24) N3(2.54,-15.24) N5(5.08,-15.24) N27(33.02,-15.24) N29(35.56,-15.24) N31(38.1,-15.24) P2(1.27,-16.51) P4(3.81,-16.51) P28(34.29,-16.51) P30(36.83,-16.51) R1(0,-17.78) R3(2.54,-17.78) R5(5.08,-17.78) R27(33.02,-17.78) R29(35.56,-17.78) R31(38.1,-17.78) T2(1.27,-19.05) T4(3.81,-19.05) T28(34.29,-19.05) T30(36.83,-19.05) U1(0,-20.32) U3(2.54,-20.32) U5(5.08,-20.32) U27(33.02,-20.32) U29(35.56,-20.32) U31(38.1,-20.32) V2(1.27,-21.59) V4(3.81,-21.59) V28(34.29,-21.59) V30(36.83,-21.59) W1(0,-22.86) W3(2.54,-22.86) W5(5.08,-22.86) W27(33.02,-22.86) W29(35.56,-22.86) W31(38.1,-22.86) Y2(1.27,-24.13) Y4(3.81,-24.13) Y28(34.29,-24.13) Y30(36.83,-24.13)
IND_SPM5030VT
  rect 2.15x2.6 smd: 1(-2.175,0) 2(2.175,0)
IND_SRP7028C
  rect 2.15x3.4 smd: 1(-2.925,0) 2(2.925,0)
SOD323-REV_MCC
  rect 1.016x0.508 smd: 1(1.194,0) 2(-1.194,0)
SOD-123-STP-REV_ST
  rect 0.991x0.686 smd: 1(-1.753,0) 2(1.753,0)
SOIC5-SOT-23_DBV-TI
  rect 0.559x1.143 smd: 1(-0.95,-1.35) 2(0,-1.35) 3(0.95,-1.35) 4(0.95,1.35) 5(-0.95,1.35)
SOIC6-DDC_TI
  rect 1.1x0.6 smd: 1(-1.35,0.95) 2(-1.35,0) 3(-1.35,-0.95) 4(1.35,-0.95) 5(1.35,0) 6(1.35,0.95)
SOIC6-VSON-HR-DMQ_TI
  rect 0.66x0.254 smd: 1(-0.65,0.5) 2(-0.65,0) 3(-0.65,-0.5)
  rect 0.991x0.229 smd: 4(0.45,-0.5) 5(0.45,0) 6(0.45,0.5)
SOIC8-DCU_TI
  rect 0.305x1.219 smd: 1(-0.75,-1.375) 2(-0.25,-1.375) 3(0.25,-1.375) 4(0.75,-1.375) 5(0.75,1.375) 6(0.25,1.375) 7(-0.25,1.375) 8(-0.75,1.375)
SOIC8-DGK_TI
  rect 0.356x1.524 smd: 1(-0.975,-2.173) 2(-0.325,-2.173) 3(0.325,-2.173) 4(0.975,-2.173) 5(0.975,2.173) 6(0.325,2.173) 7(-0.325,2.173) 8(-0.975,2.173)
SOIC8-DSG_TI
  rect 0.787x0.305 smd: 1(-1.1,0.75) 2(-1.1,0.25) 3(-1.1,-0.25) 4(-1.1,-0.75) 5(1.1,-0.75) 6(1.1,-0.25) 7(1.1,0.25) 8(1.1,0.75)
  rect 0.889x1.702 smd: 9(0,0)
SOIC24-PWP_TI_A
  rect 0.356x1.524 smd: 1(-3.576,-2.946) 2(-2.926,-2.946) 3(-2.276,-2.946) 4(-1.626,-2.946) 5(-0.975,-2.946) 6(-0.325,-2.946) 7(0.325,-2.946) 8(0.975,-2.946) 9(1.626,-2.946) 10(2.276,-2.946) 11(2.926,-2.946) 12(3.576,-2.946) 13(3.576,2.946) 14(2.926,2.946) 15(2.276,2.946) 16(1.626,2.946) 17(0.975,2.946) 18(0.325,2.946) 19(-0.325,2.946) 20(-0.975,2.946) 21(-1.626,2.946) 22(-2.276,2.946) 23(-2.926,2.946) 24(-3.576,2.946)
  rect 5.588x2.54 smd: 25(0,0)
SOT23-3_FC
  rect 1.016x1.372 smd: 1(0.94,1.092) 2(-0.94,1.092) 3(0,-1.092)
SOT223AVX
  rect 1.168x2.184 smd: 1(-2.286,-3.099) 2(0,-3.099) 3(2.286,-3.099)
  rect 3.607x2.184 smd: 4(0,3.099)
SOT-490-SC89-3_FC
  rect 0.508x0.66 smd: 1(-0.5,-0.57) 2(0.5,-0.57) 3(0,0.57)
TP-48RD
  round 1.219 smd: 1(0,0)
TP-5006-GND_KEY
  round 2.54 hole 1.6: 1(0,0)
unnamed#2
  round 0.762 smd: 1(0,0)
unnamed#3
  round 1.27 hole 4.801 unplated: (0,0)

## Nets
GND: C1.1 C2.1 C3.1 C4.1 C5.1 C6.1 C17.1 C18.1 C19.1 C20.1 C21.1 C22.1 C23.1 C24.1 C27.2 C28.1 C29.1 C31.2 C33.1 C34.2 C36.2 C37.1 C38.1 C39.1 C40.1 C41.1 C42.1 C43.1 C44.1 C45.1 C46.1 C47.1 C48.1 C49.1 C50.1 C51.1 C52.1 C53.1 C54.1 C55.1 C56.1 C57.1 C58.1 C59.1 C60.1 C61.1 C62.1 C63.1 C64.1 C65.1 C66.1 C67.1 C68.1 C69.1 C70.1 C71.1 C72.1 C73.1 C74.1 C75.1 C76.1 C77.1 C78.1 C79.1 C80.1 C81.1 C82.1 C83.1 C84.1 C85.1 C86.1 C87.1 C88.1 C89.1 C90.1 C91.2 C92.2 C93.1 C94.1 C95.1 C96.1 C97.1 C98.1 C99.1 C100.1 C101.1 C102.1 C103.1 C104.1 C105.1 C106.1 C107.1 C108.1 C109.1 C110.1 C111.1 C112.1 C113.1 C114.1 C115.1 C116.1 C117.1 C118.1 C119.1 C120.1 C121.1 C122.1 C123.1 C124.1 C125.1 C126.1 C127.1 C128.1 C129.1 C130.1 C131.1 C132.1 C133.1 C134.1 C135.1 C136.1 C137.1 C138.1 C139.1 C140.1 C141.1 C142.1 C143.1 C144.1 C145.1 C146.1 C147.1 C148.1 C149.1 C150.1 C151.1 C152.1 C153.1 C154.1 C155.1 C156.1 C157.1 C158.1 C159.1 C160.1 C161.1 C162.1 C163.1 C164.1 C165.1 C166.1 C167.1 C168.1 C169.1 C170.1 C171.1 C172.1 C173.1 C174.1 C175.1 C177.1 C179.1 C181.1 C182.1 C183.1 C184.1 C185.1 C186.1 C187.1 C188.1 C189.1 C190.1 C191.2 C192.1 C193.1 C195.1 C196.1 C197.1 C199.1 C200.1 C201.1 D1.1 D6.2(CATHODE) FB3.1 FB4.1 J1.10 J1.13 J1.16 J1.19 J1.20 J1.23 J1.24 J1.27 J1.28 J1.31 J1.32 J1.35 J1.36 J1.39 J1.40 J1.43 J1.44 J1.47 J1.48 J1.51 J1.52 J1.53 J1.54 J1.55 J1.56 J1.57 J1.58 J1.59 J1.60 J1.61 J2.10 J2.13 J2.16 J2.19 J2.20 J2.23 J2.24 J2.27 J2.28 J2.31 J2.32 J2.35 J2.36 J2.39 J2.40 J2.43 J2.44 J2.47 J2.48 J2.51 J2.52 J2.53 J2.54 J2.55 J2.56 J2.57 J2.58 J2.59 J2.60 J2.61 J3.10 J3.13 J3.16 J3.19 J3.20 J3.23 J3.24 J3.27 J3.28 J3.31 J3.32 J3.35 J3.36 J3.39 J3.40 J3.43 J3.44 J3.47 J3.48 J3.51 J3.52 J3.53 J3.54 J3.55 J3.56 J3.57 J3.58 J3.59 J3.60 J3.61 J4.10 J4.13 J4.16 J4.19 J4.20 J4.23 J4.24 J4.27 J4.28 J4.31 J4.32 J4.35 J4.36 J4.39 J4.40 J4.43 J4.44 J4.47 J4.48 J4.51 J4.52 J4.53 J4.54 J4.55 J4.56 J4.57 J4.58 J4.59 J4.60 J4.61 J5.4 R10.1 R19.2 R25.1 R27.1 R29.1 R35.1 R36.2 R42.1 R43.1 R44.1 R57.1 R59.1 R65.1 TP2.1 TP4.1 TP7.1 TP8.1 TP11.1 TP12.1 TP13.1 TP14.1 U6.5 U6.9 U7.2 U8.5(VDD) U9.2 U10.7 U10.8 U10.11 U10.19 U10.25 U12.2(S) U13.2(S) U14.2(S) U15.1 U16.A1 U16.AA3 U16.AC3 U16.AC29 U16.AD2 U16.AD6 U16.AD20 U16.AE7 U16.AE9 U16.AE11 U16.AE17 U16.AE21 U16.AE25 U16.AE29 U16.AF8 U16.AF14 U16.AF16 U16.AG3 U16.AG11 U16.AG13 U16.AG15 U16.AG17 U16.AG19 U16.AG21 U16.AG23 U16.AG25 U16.AG27 U16.AG29 U16.AH2 U16.AH4 U16.AH6 U16.AH22 U16.AH26 U16.AH28 U16.AJ3 U16.AJ7 U16.AJ9 U16.AJ13 U16.AJ15 U16.AJ17 U16.AJ19 U16.AJ23 U16.AJ25 U16.AJ27 U16.AK4 U16.AK6 U16.AK8 U16.AK12 U16.AK16 U16.AK20 U16.AK28 U16.AK30 U16.AL3 U16.B2 U16.B10 U16.B28 U16.B30 U16.C3 U16.C5 U16.C7 U16.C9 U16.C11 U16.C15 U16.C17 U16.C19 U16.C23 U16.C25 U16.D2 U16.D22 U16.D28 U16.D30 U16.E3 U16.E7 U16.E9(VSSA#E9) U16.E11 U16.E13 U16.E15 U16.E19 U16.E21 U16.E25 U16.E31 U16.F14 U16.G3 U16.G5 U16.G7 U16.G9 U16.G13 U16.G17 U16.G19 U16.G21 U16.G23 U16.G25 U16.G27 U16.G29 U16.H2 U16.H6 U16.H30 U16.J3 U16.J29 U16.K30 U16.L29 U16.M2 U16.M28 U16.M30 U16.N3 U16.R3 U16.R29 U16.T30 U16.U3 U16.U29 U16.V2 U16.W3 U16.W29 U16.Y2 U17.5 U18.4 U19.2 U19.4 U22.3 U23.3 U24.4 U25.4
VDD_DMD: C40.2 C42.2 C43.2 C45.2 C46.2 C47.2 C48.2 C49.2 C50.2 C51.2 C52.2 C53.2 C54.2 C55.2 C56.2 C57.2 C59.2 C60.2 C61.2 C62.2 C63.2 C64.2 C65.2 C66.2 C67.2 C69.2 C70.2 C71.2 C72.2 C73.2 C74.2 C75.2 C76.2 C78.2 C79.2 C80.2 C81.2 C83.2 C84.2 C85.2 C86.2 C87.2 C88.2 C89.2 C91.1 C92.1 C93.2 C95.2 C99.2 C100.2 C101.2 C102.2 C103.2 C104.2 C105.2 C107.2 C109.2 C110.2 C111.2 C112.2 C114.2 C116.2 C117.2 C118.2 C119.2 C120.2 C121.2 C122.2 C125.2 C126.2 C127.2 C129.2 C130.2 C131.2 C132.2 C133.2 C134.2 C143.2 C144.2 C145.2 C146.2 C147.2 C150.2 C151.2 C152.2 C153.2 C154.2 C156.2 C157.2 C164.2 C166.2 C167.2 C171.2 C196.2 C200.2 R58.2 R61.2 TP15.1 U16.A3 U16.A29 U16.AA29 U16.AB4 U16.AD8 U16.AD10 U16.AD12 U16.AD28 U16.AE13 U16.AE15 U16.AF6 U16.AF10 U16.AF12 U16.AF18 U16.AF22 U16.AF24 U16.AF26 U16.AF28 U16.AH10 U16.AH12 U16.AH14 U16.AH16 U16.AH18 U16.AJ1 U16.AJ5 U16.AJ11 U16.AJ21 U16.AJ29 U16.AJ31 U16.AK2 U16.AL29 U16.B4 U16.C1 U16.C13 U16.C21 U16.C29 U16.C31 U16.D8 U16.D12 U16.D16 U16.D18 U16.D20 U16.D24 U16.F8 U16.F10 U16.F12 U16.F16 U16.F18 U16.F20 U16.H16 U16.H18 U16.H20 U16.H22 U16.H24 U16.H28 U16.K4 U16.L3 U16.M4 U16.N29 U16.P4 U16.P28 U16.T4 U16.T28 U16.V4 U16.V28 U16.Y28 U22.5 U23.5
VDDA_DMD: C39.2 C41.2 C44.2 C58.2 C68.2 C77.2 C82.2 C90.2 C94.2 C96.2 C97.2 C98.2 C106.2 C108.2 C113.2 C115.2 C123.2 C124.2 C128.2 C140.2 C141.2 C142.2 C148.2 C149.2 C155.2 C158.2 C159.2 C165.2 C168.2 C169.2 C170.2 C199.2 R62.2 R64.2 TP16.1 U16.AB28 U16.AD14 U16.AD16 U16.AD18 U16.AD22 U16.AD24 U16.AE19 U16.AE27 U16.AF20 U16.AH20 U16.AH24 U16.D10 U16.D14 U16.F6 U16.G11 U16.G15 U16.H8 U16.H10 U16.H12 U16.H14 U16.H26 U16.K28
AMUX_OUT: J8.1 U16.E17
DCLK_AN: J1.34 U16.N1
DCLK_AP: J1.33 U16.P2
DCLK_BN: J2.34 U16.B18
DCLK_BP: J2.33 U16.A19
DCLK_CN: J3.34 U16.AL11
DCLK_CP: J3.33 U16.AL13
DCLK_DN: J4.34 U16.AH30
DCLK_DP: J4.33 U16.AG31
DD_A0N: J1.18 U16.F2
DD_A0P: J1.17 U16.E1
DD_A1N: J1.22 U16.G1
DD_A1P: J1.21 U16.J1
DD_A2N: J1.26 U16.B6
DD_A2P: J1.25 U16.A5
DD_A3N: J1.30 U16.L1
DD_A3P: J1.29 U16.K2
DD_A4N: J1.38 U16.A7
DD_A4P: J1.37 U16.B8
DD_A5N: J1.42 U16.A9
DD_A5P: J1.41 U16.A11
DD_A6N: J1.46 U16.T2
DD_A6P: J1.45 U16.R1
DD_A7N: J1.50 U16.U1
DD_A7P: J1.49 U16.W1
DD_B0N: J2.18 U16.B12
DD_B0P: J2.17 U16.A13
DD_B1N: J2.22 U16.R31
DD_B1P: J2.21 U16.P30
DD_B2N: J2.26 U16.A15
DD_B2P: J2.25 U16.B14
DD_B3N: J2.30 U16.B16
DD_B3P: J2.29 U16.A17
DD_B4N: J2.38 U16.A21
DD_B4P: J2.37 U16.B20
DD_B5N: J2.42 U16.L31
DD_B5P: J2.41 U16.N31
DD_B6N: J2.46 U16.J31
DD_B6P: J2.45 U16.G31
DD_B7N: J2.50 U16.A23
DD_B7P: J2.49 U16.B22
DD_C0N: J3.18 U16.AL5
DD_C0P: J3.17 U16.AL7
DD_C1N: J3.22 U16.AF2
DD_C1P: J3.21 U16.AG1
DD_C2N: J3.26 U16.AE1
DD_C2P: J3.25 U16.AC1
DD_C3N: J3.30 U16.AB2
DD_C3P: J3.29 U16.AA1
DD_C4N: J3.38 U16.AL9
DD_C4P: J3.37 U16.AK10
DD_C5N: J3.42 U16.AK14
DD_C5P: J3.41 U16.AL15
DD_C6N: J3.46 U16.AL17
DD_C6P: J3.45 U16.AK18
DD_C7N: J3.50 U16.AL21
DD_C7P: J3.49 U16.AL19
DD_D0N: J4.18 U16.AK22
DD_D0P: J4.17 U16.AL23
DD_D1N: J4.22 U16.AK24
DD_D1P: J4.21 U16.AL25
DD_D2N: J4.26 U16.AL27
DD_D2P: J4.25 U16.AK26
DD_D3N: J4.30 U16.U31
DD_D3P: J4.29 U16.V30
DD_D4N: J4.38 U16.AE31
DD_D4P: J4.37 U16.AF30
DD_D5N: J4.42 U16.Y30
DD_D5P: J4.41 U16.W31
DD_D6N: J4.46 U16.AA31
DD_D6P: J4.45 U16.AB30
DD_D7N: J4.50 U16.AC31
DD_D7P: J4.49 U16.AD30
DMD_EN_ARSTZ: J1.9 U23.2
DMD_EN_ARSTZ_BUF: R44.2 U16.AE23 U16.E27 U16.Y4 U23.4(Y)
DMD_PWR_EN: J1.7 J6.2 R10.2 R43.2 R60.1 R63.1 U6.3 U12.1 U24.1 U25.1
DMD_RESERVED: J2.11 U22.2
DMD_RSVD_BUF: R45.2 U22.4(Y)
DMD_TP0: J10.1 U16.AH8
DMD_TP1: J10.2 U16.AG7
DMD_TP2: J10.3 U16.AG9
DMUX_LATCHED: J4.7 U18.5
DMUX_OUT: J8.2 R57.2 U16.E29 U18.1
I2C_SCL_3P3V: J2.14 J5.1 R7.1 U17.8
I2C_SDA_3P3V: J2.15 J5.2 R6.1 U17.7
LATCH_CLEAR_Z: J4.8 R56.1 U18.6
LS_CLK_N: J1.11 U16.A25
LS_CLK_P: J1.12 U16.B24
LS_RDATA_A: J1.8 U16.F24
LS_RDATA_B: J2.7 U16.D26
LS_RDATA_C: J2.8 U16.F30
LS_RDATA_D: J2.9 U16.C27
LS_WDATA_N: J1.14 U16.A27
LS_WDATA_P: J1.15 U16.B26
MBRST0: J9.1 U16.N27
MBRST1: J9.2 U16.R27
MBRST2: J9.3 U16.N5
MBRST3: J9.4 U16.L5
MBRST4: J9.5 U16.L27
MBRST5: J9.6 U16.J27
MBRST6: J9.7 U16.R5
MBRST7: J9.8 U16.J5
MBRST8: J9.9 U16.U27
MBRST9: J9.10 U16.W5
MBRST10: J9.11 U16.AA5
MBRST11: J9.12 U16.W27
MBRST12: J9.13 U16.AC27
MBRST13: J9.14 U16.U5
MBRST14: J9.15 U16.AC5
MBRST15: J9.16 U16.AA27
P1P8V_LDO: C179.2 C181.2 J6.1 R12.2 R53.2 R54.2 R55.2 R56.2 TP17.1 U7.5(VDD) U9.5(VDD) U18.8(VCC)
P3P3V: C1.2 C2.2 C3.2 C4.2 C5.2 C6.2 C17.2 C175.2 C195.2 C197.2 C201.2 J5.3 R1.2 R2.2 R3.2 R4.2 R6.2 R7.2 R9.2 R39.2 R60.2 R63.2 TP1.1 U6.1 U6.2 U6.4 U17.1(VCC) U19.1 U24.6(VIN) U25.6(VIN)
POWERGOOD: D1.2(CATHODE) J2.12 R12.1 R21.2 TP5.1 U7.1 U7.6 U9.1 U9.6 U24.2 U25.2
SW: C26.2 D2.1 L2.2 U10.5 U10.6
V_BIAS: C172.2 C173.2 C174.2 C188.2 C189.2 C190.2 C191.1 C192.2 C193.2 R20.2 R37.2 R50.1 TP10.1 U16.AD4 U16.AE3 U16.D4
V_BIAS_CPI: C36.1 C37.2 C38.2 D9.2(CATHODE) R41.2 U10.16
V_OFFSET: C135.2 C136.2 C137.2 C138.2 C139.2 C182.2 C183.2 C184.2 D7.1 R18.2 R31.2 R48.2 TP6.1 U16.AD26 U16.AE5 U16.F4 U16.F26 U16.H4
V_RESET: C160.2 C161.2 C162.2 C163.2 C185.2 C186.2 C187.2 R26.1 R33.2 R49.2 TP9.1 U8.2 U11.2(S) U16.AF4 U16.AG5 U16.D6 U16.E5
N16772038: J4.1 J4.2 J4.3 J4.4 J4.5 J4.6 R4.1
N16773260: J1.1 J1.2 J1.3 J1.4 J1.5 J1.6 R2.1
N16773766: J2.1 J2.2 J2.3 J2.4 J2.5 J2.6 R1.1
N16774650: J3.1 J3.2 J3.3 J3.4 J3.5 J3.6 R3.1
N16775308: FB3.2 J7.3
N16775316: FB4.2 J7.2
N16775420: FB1.2 J7.4
N16775848: FB1.1 FB2.1 R9.1
N16783807: R24.1 R27.2 U9.4
N16783825: R20.1 R24.2 U9.3
N16783989: R23.1 R26.2 U8.4
N16784029: R19.1 R23.2 U8.3
N16784057: R21.1 U8.1 U8.6
N16784127: R18.1 R22.2 U7.3
N16784131: R22.1 R25.2 U7.4
N16784325: R39.1 U12.3 U13.1 U14.1 U15.2(S)
N16784355: R37.1 R40.2
N16784357: R40.1 U13.3
N16784417: C19.2 C20.2 C21.2 L2.1 U6.7 U6.8(VOUT#8) U10.4(VIN) U10.13 U10.24
N16784489: D8.2 U14.3
N16784491: D8.1(CATHODE) R38.1
N16784593: C22.2 C23.2 C24.2 C25.2 C177.2 D2.2(CATHODE) R28.2 R48.1 U10.9
N16784602: C25.1 R28.1 R29.2 U10.1
N16784669: C26.1 D3.2(CATHODE) D4.1
N16784699: C31.1 D4.2(CATHODE) D5.1
N16784701: C30.1 D5.2(CATHODE) D6.1
N16784732: C27.1 C28.2 C29.2 D3.1 R30.2 R49.1
N16784789: C30.2 U10.18
N16784866: R30.1 R32.2 U10.21
N16784882: C33.2 R32.1 U10.20
N16784896: C35.2 U10.17
N16784898: R41.1 R42.2 U10.12
N16784904: C18.2 U6.6
N16784908: C35.1 D7.2(CATHODE) D9.1
N16785040: C32.2 R36.1
N16785042: C32.1 U10.22
N16785060: C34.1 U10.2
N16795774: R34.2 U11.3
N16795788: R33.1 U11.1 U15.3
N16797776: R34.1 R35.2
N16804439: R45.1 U16.F28
N16806468: R47.2 U17.3
N16806470: R46.2 U17.2
N16806960: C176.2 R46.1 U16.F22
N16807032: C176.1 R47.1 U16.E23
N16928315: R50.2 U10.15
N16943816: R53.1 U18.2
N16945352: R54.1 U18.7
N16947306: R55.1 U19.3(VOUT)
N17048439: L3.1 U24.5
N17048462: C194.2 L3.2 R61.1
N17048467: C194.1 R58.1 R59.2 U24.3
N17053433: L4.1 U25.5
N17053437: C198.2 L4.2 R62.1
N17053493: C198.1 R64.1 R65.2 U25.3
N167753000: FB2.2 J7.1
N167843971: R31.1 R38.2

Pads without a net: FID 1; FID#2 1; FID#3 1; FID#4 1; FID#5 1; FID#6 1; J3 7 8 9 11 12 14 15; J4 9 11 12 14 15; U10 3 10 14 23; U17 4 6; U18 3; U22 1; U23 1

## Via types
v1: diameter 0.61, hole 0.305, TOP to BOTTOM, 1109 vias

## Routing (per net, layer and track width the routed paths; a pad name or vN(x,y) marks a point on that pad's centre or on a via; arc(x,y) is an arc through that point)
GND: length 990.8
  TOP w0.203: v1(127.8,114.45) 127.8,114.98 127.67,115.12 J2.13 ; J2.19 124.67,115 v1(124.17,114.5) J2.20 ; J1.28 v1(76.36,114.59) 76.86,115.09 J1.27 ; J2.39 v1(114.68,114.48) 114.18,114.98 J2.40 ; J1.32 v1(74.36,114.55) 74.86,115.05 J1.31 ; J2.36 v1(116.18,114.58) 116.68,115.08 J2.35 ; v1(110.15,114.63) 110.18,114.66 ; 110.18,114.66 J2.48 ; 110.18,114.66 110.68,115.16 J2.47 ; J1.43 68.86,114.82 v1(69.36,114.32) 69.31,114.27 68.62,114.27 68.36,114.53 J1.44 ; v1(129.33,112.37) 129.02,112.67 129.02,113.46 129.15,113.59 129.15,115.22 129.17,115.24 J2.10 ; v1(107.79,115.29) 108.45,115.29 108.68,115.52 J2.51 ; J1.40 70.36,114.98 v1(70.86,114.48) J1.39 ; J2.28 v1(120.18,114.59) 120.68,115.09 J2.27 ; v1(89.93,91.74) 89.29,91.1 U24.4 ; J2.24 v1(122.17,114.54) 122.67,115.04 J2.23 ; U25.4 68.97,99.36 v1(69.61,100) ; J1.13 83.86,114.9 v1(84.11,114.65) ; v1(14.52,89.03) 14.74,88.81 U6.5 ; J1.16 v1(82.36,114.51) ; J1.51 64.86,115.52 64.63,115.29 v1(63.97,115.29) ; J2.16 v1(126.17,114.51) ; 66.36,114.66 J1.48 ; J1.36 v1(72.36,114.58) 72.86,115.08 J1.35 ; J2.31 118.68,115.05 v1(118.18,114.55) J2.32 ; v1(85.23,112.27) 85.23,115.11 85.36,115.24 J1.10 ; J2.44 112.18,114.53 112.44,114.27 113.13,114.27 v1(113.18,114.32) 112.68,114.82 J2.43 ; J1.19 80.86,115 v1(80.36,114.5) J1.20 ; J1.24 v1(78.36,114.54) 78.86,115.04 J1.23
  TOP w0.254: v1(13.22,73.68) 12.93,73.98 U10.8 ; U17.5 v1(117.96,11.75) ; v1(14.49,74.95) 15.28,74.95 15.61,75.28 U10.19 ; U18.4 v1(105.07,92.88) ; v1(13.22,72.41) 13.02,72.21 12.54,72.21 12.36,72.03 U10.11 ; J1.47 66.86,115.16 v1(66.34,114.63) ; U10.7 12.9,74.63 v1(13.22,74.95)
  TOP w0.381: D1.1 v1(119.27,89.2) ; v1(70.6,65.81) 69.88,65.81 C106.1 ; v1(106.06,21.49) 105.93,21.61 C138.1 ; C95.1 v1(54.09,4.58) ; v1(13.1,117.63) FB4.1 v1(13.1,113.56) ; v1(107.59,32.18) 107.59,32.9 C63.1 ; v1(101.08,64.54) 100.36,64.54 C55.1 ; R35.1 v1(108.26,104.91) ; v1(98.09,9.8) 98.81,9.8 C65.1 ; v1(42.69,26.92) 42.69,26.2 C64.1 ; v1(39.51,22.48) 39.51,21.75 C50.1 ; C34.2 v1(8.14,81.36) ; C144.1 107.59,36.71 v1(107.59,35.99) ; C47.1 55.91,65.18 v1(56.63,65.18) ; C77.1 95.91,62.64 v1(96.64,62.64) ; C156.1 v1(97.57,7.24) ; v1(107.59,28.37) 107.59,29.09 C97.1 ; C73.1 85.16,2.41 v1(84.68,2.89) ; C58.1 71.78,65.81 v1(72.51,65.81) ; v1(45.23,47.88) 45.23,47.15 C48.1 ; C112.1 75.59,65.81 v1(76.32,65.81) ; C105.1 46.5,10.32 v1(46.5,11.05) ; C78.1 42.69,35.72 v1(42.69,36.45) ; v1(90.47,4.09) 91.19,4.09 C129.1 ; v1(43.83,43.2) C173.1 ; v1(40.15,44.07) 40.15,43.34 C131.1 ; C39.1 105.05,50.05 v1(105.05,49.33) ; v1(64.25,62.64) 63.53,62.64 C103.1 ; v1(60.44,62.64) 59.72,62.64 C107.1 ; v1(109.77,18.15) 109.44,17.83 U23.3 ; v1(103.14,8.69) 103.14,9.41 C53.1 ; v1(105.05,43.61) 105.05,44.33 C139.1 ; C142.1 81.31,65.81 v1(82.03,65.81) ; C79.1 42.69,33.82 v1(42.69,34.54) ; C43.1 105.05,25.28 v1(105.05,24.56) ; v1(94.28,6.63) 95,6.63 C62.1 ; R27.1 v1(134.4,91.63) ; v1(50.31,55.5) 50.31,54.77 C162.1 ; v1(102.51,58.85) 102.51,59.57 C155.1 ; C93.1 v1(50.28,5.85) ; C101.1 42.69,28.1 v1(42.69,28.83) ; C20.1 v1(8.14,78.26) ; v1(98.54,62) 97.82,62 C40.1 ; C82.1 99.72,60.73 v1(100.45,60.73) ; C85.1 45.23,19.85 v1(45.23,20.57) ; C151.1 101.24,11.95 v1(101.24,11.23) ; C84.1 84.48,62.64 v1(85.21,62.64) ; C33.1 21.65,76.74 22.27,76.12 v1(22.52,76.12) ; v1(94.73,62.64) 94.01,62.64 C169.1 ; v1(105.05,51.23) 105.05,51.95 C41.1 ; R43.1 v1(94.25,98.45) ; C72.1 41.65,9.22 v1(41.85,9.02) ; v1(88.56,3.45) 89.29,3.45 C61.1 ; v1(86.66,3.45) 87.38,3.45 C60.1 ; v1(27.04,78.41) 26.56,77.93 C31.2 ; v1(42.69,32.64) 42.69,31.91 C146.1 ; v1(14.65,92.35) 14.38,92.09 C17.1 ; v1(52.21,57.4) 52.21,56.68 C126.1 ; v1(47.77,9.14) 47.77,8.42 C104.1 ; C135.1 45.23,41.44 v1(45.23,42.16) ; v1(106.06,18.95) C42.1 ; C2.1 v1(26.75,96.66) ; C141.1 105.05,48.14 v1(105.05,47.42) ; v1(108.22,40.44) 108.22,41.16 C152.1 ; v1(116.6,91.92) 117.25,91.27 R25.1 ; C154.1 v1(52.19,5.22) ; C80.1 42.69,37.63 v1(42.69,38.35) ; C145.1 107.59,38.62 v1(107.59,37.9) ; v1(5.48,78.76) 5.48,78 5.1,77.62 C22.1 ; C38.1 v1(27.19,69.95) ; C5.1 v1(23.02,96.66) ; C163.1 48.4,52.87 v1(48.4,53.59) ; C134.1 46.5,50.96 v1(46.5,51.69) ; C150.1 45.23,25.56 v1(45.23,26.29) ; C166.1 82.58,62.64 v1(83.3,62.64) ; v1(105.05,41.71) 105.05,42.43 C130.1 ; v1(45.23,49.78) 45.23,49.06 C132.1 ; C168.1 104.41,53.86 v1(104.41,53.14) ; C153.1 57.81,62.64 v1(58.54,62.64) ; v1(44.21,24.15) C136.1 ; C52.1 108.22,21.47 v1(108.22,20.75) ; v1(78.22,68.99) 77.5,68.99 C56.1 ; C100.1 42.69,30.01 v1(42.69,30.73) ; C148.1 105.05,23.38 v1(105.05,22.66) ; v1(101.87,13.13) 101.87,13.85 C171.1 ; v1(107.59,30.28) 107.59,31 C125.1 ; C143.1 107.59,34.81 v1(107.59,34.09) ; C29.1 v1(25.81,87.9) ; C111.1 v1(55.25,59.49) ; C66.1 105.05,40.52 v1(105.05,39.8) ; U9.2 v1(128.67,94) ; U7.2 v1(114.06,94) ; v1(92.83,62.64) 92.1,62.64 C165.1 ; v1(45.86,12.95) 45.86,12.23 C164.1 ; C99.1 45.23,14.13 v1(45.23,14.86) ; C44.1 73.69,65.81 v1(74.41,65.81) ; v1(87.11,62.64) 86.39,62.64 C140.1 ; C57.1 105.05,17.66 v1(105.05,16.94) ; v1(80.13,65.81) 79.4,65.81 C68.1 ; v1(62.35,62.64) 61.62,62.64 C102.1 ; v1(31.64,105.05) FB3.1 v1(29.35,106.58) ; C174.1 45.23,17.94 v1(45.23,18.67) ; v1(44.21,21.61) C137.1 ; U12.2 v1(94.19,100.42) ; v1(105.05,45.52) 105.05,46.24 C159.1 ; C37.1 v1(25.29,70.03) ; v1(92.37,4.72) 93.1,4.72 C67.1 ; U13.2 v1(97.31,100.42) ; v1(78.22,65.81) 77.5,65.81 C158.1 ; R36.2 v1(20.84,81.33) ; C147.1 96.91,8.53 v1(96.18,8.53) ; C170.1 88.29,62.64 v1(89.02,62.64) ; C6.1 v1(27.83,95.68) ; C90.1 v1(67.43,3.95) ; C4.1 v1(27.58,101.78) ; v1(108.86,48.06) 108.86,48.78 C54.1 ; C59.1 83.57,3.45 v1(82.85,3.45) ; D6.2 v1(25.16,71.63) ; C36.2 v1(23.38,71.09) ; C108.1 67.97,65.81 v1(68.7,65.81) ; C45.1 103.78,15.76 v1(103.78,15.04) ; C81.1 v1(56,3.95) ; v1(66.16,62.64) 65.43,62.64 C110.1 ; R42.1 v1(10.37,68.08) ; R10.1 v1(50.22,115.07) ; C98.1 107.59,27.19 v1(107.59,26.47) ; C51.1 95,2.82 v1(94.28,2.82) ; C149.1 v1(65.52,3.95) ; C28.1 v1(25.81,84.24) ; C83.1 103.78,55.76 v1(103.78,55.04) ; C127.1 v1(53.98,57.58) ; C23.1 v1(4.86,82.9) ; C157.1 45.23,16.04 v1(45.23,16.76) ; v1(101.82,99.67) 102.05,99.9 U15.1 ; U14.2 v1(101.22,100.42) ; C24.1 v1(6.99,74.61) ; C96.1 102.51,57.67 v1(102.51,56.95) ; v1(90.92,62.64) 90.2,62.64 C167.1 ; C94.1 v1(63.62,3.95) ; C1.1 v1(25,96.66) ; C109.1 67.34,62.64 v1(68.06,62.64) ; C21.1 v1(19.09,81.19) ; C160.1 v1(57.9,3.95) ; C49.1 v1(49.65,2.68) ; C175.1 v1(113.44,14.39) ; v1(43.45,44.35) C172.1 ; C133.1 42.69,39.53 v1(42.69,40.26) ; U8.5 v1(126.23,94) ; C3.1 v1(23.05,101.78) ; R19.2 v1(120.65,91.76)
  TOP w0.508: TP11.1 32.12,78.29 ; TP11.1 29.89,80.51 ; TP11.1 32.12,80.51 ; TP11.1 29.89,78.29 ; J1.60 v1(95.76,121.6) ; 12.75,99.24 TP2.1 ; TP2.1 12.75,101.46 ; TP2.1 14.97,101.46 ; TP2.1 14.97,99.24 ; C92.2 62.32,80.1 62.68,80.46 v1(62.68,81.38) ; C92.2 v1(60.21,84.35) ; C92.2 v1(57.35,80.1) ; C48.1 44.64,46.57 44.64,46.2 44.31,45.87 C188.1 ; C161.1 v1(59.72,3.95) ; R65.1 v1(72.2,93.22) ; C70.1 37.58,45.49 v1(37.94,45.13) ; J2.56 v1(118.67,122.84) ; C179.1 v1(105.55,96.54) ; 8.3,57.33 TP13.1 ; TP13.1 8.3,59.55 ; TP13.1 10.53,57.33 ; TP13.1 10.53,59.55 ; C181.1 v1(39.51,92.99) ; C75.1 109.9,45.62 v1(109.57,45.29) ; 24.18,92.57 TP8.1 ; TP8.1 26.4,90.35 ; TP8.1 24.18,90.35 ; TP8.1 26.4,92.57 ; C184.1 106.06,20.34 106.42,19.99 106.85,19.99 v1(107.1,19.73) ; v1(83.86,67.26) 84.09,67.49 C76.1 ; C27.2 v1(19.96,85.11) ; 43.23,72.57 TP14.1 ; TP14.1 45.45,72.57 ; TP14.1 43.23,74.79 ; J1.52 v1(61.86,114.56) ; TP7.1 4.81,68.13 ; TP7.1 2.59,70.35 ; TP7.1 2.59,68.13 ; TP7.1 4.81,70.35 ; C193.1 v1(22.11,61.62) ; v1(48.06,59.29) 48.54,58.81 48.54,58.44 48.91,58.06 C185.1 ; J2.58 v1(128.68,122.79) ; C182.1 v1(41.02,41.3) ; J2.59 v1(133.68,122.8) ; v1(38.14,34.75) 37.84,34.44 C71.1 ; 73.71,100.51 TP4.1 ; TP4.1 75.93,102.73 ; TP4.1 73.71,102.73 ; TP4.1 75.93,100.51 ; J2.61 v1(136.68,114.43) ; J2.54 v1(108.67,122.84) ; TP12.1 141.97,27.49 ; TP12.1 141.97,29.71 ; TP12.1 139.75,29.71 ; TP12.1 139.75,27.49 ; J1.57 v1(81.58,121.32) ; v1(96.28,79.02) 94.25,79.02 93.87,79.4 C91.2 ; J2.60 v1(139.57,121.6) ; J2.53 v1(100.74,119.32) ; J2.55 v1(113.67,122.78) ; v1(36.85,93.24) 36.34,93.75 36.34,94.51 35.83,95.02 U19.2 ; J1.54 v1(64.86,122.84) ; C19.1 13.99,69.75 v1(13.61,70.13) ; C191.2 v1(19.83,60.73) ; J5.4 v1(119.4,6.37) ; v1(110.28,25.37) 110.53,25.12 C74.1 ; J2.52 v1(105.67,114.56) ; J1.61 v1(92.86,114.43) ; J1.53 v1(56.92,119.32) ; C183.1 43.27,22.88 v1(42.92,22.53) ; U22.3 114.97,23.96 114.75,24.18 114.75,24.36 v1(114.27,24.84) ; J1.56 v1(74.86,122.84) ; C201.1 v1(31.77,92.99) ; R29.1 v1(7.51,89.69) ; R59.1 v1(88.79,83.69) ; C91.2 93.87,81.56 94.23,81.92 v1(96.18,81.92) ; C91.2 v1(91.27,80.1) ; J1.59 v1(89.86,122.8) ; v1(6.75,90.45) 6.37,90.07 C177.1 ; C128.1 v1(61.62,3.95) ; J2.57 v1(125.24,121.32) ; C192.1 v1(24.02,61.62) ; v1(65.8,65.94) 65.52,66.22 C69.1 ; R57.1 v1(102.11,96.15) ; J1.58 v1(84.86,122.79) ; C196.1 v1(94.63,90.07) ; v1(33.21,101.8) U19.4 v1(38.57,101.8) ; C186.1 v1(51.61,58.47) ; C199.1 v1(64.15,85.72) ; J1.55 v1(69.86,122.78)
  LY2-SIG w0.508: TP11.1 32.12,78.29 ; TP11.1 29.89,78.29 ; TP11.1 32.12,80.51 ; 43.23,74.79 TP14.1 ; TP14.1 v1(44.34,71.4) ; TP14.1 45.45,72.57 ; TP14.1 43.23,72.57 ; TP14.1 45.45,74.79 ; 12.75,99.24 TP2.1 ; TP2.1 14.97,99.24 ; TP2.1 12.75,101.46 ; TP2.1 14.97,101.46 ; TP12.1 141.97,29.71 ; TP12.1 139.75,27.49 ; TP12.1 141.97,27.49 ; TP12.1 139.75,29.71 ; TP13.1 10.53,59.55 ; TP13.1 8.3,57.33 ; TP13.1 10.53,57.33 ; TP13.1 8.3,59.55 ; 24.18,92.57 TP8.1 ; TP8.1 26.4,90.35 ; TP8.1 24.18,90.35 ; TP8.1 26.4,92.57 ; TP4.1 75.93,102.73 ; TP4.1 73.71,102.73 ; TP4.1 73.71,100.51 ; TP4.1 75.93,100.51 ; TP7.1 4.81,70.35 ; TP7.1 4.81,68.13 ; TP7.1 2.59,70.35 ; TP7.1 2.59,68.13
  LY3-GND w0.508: TP12.1 141.97,27.49 ; TP12.1 139.75,27.49 ; TP12.1 141.97,29.71 ; TP12.1 139.75,29.71 ; 2.59,70.35 TP7.1 ; TP7.1 4.81,70.35 ; TP7.1 2.59,68.13 ; TP7.1 4.81,68.13 ; 8.3,59.55 TP13.1 ; TP13.1 10.53,57.33 ; TP13.1 10.53,59.55 ; TP13.1 8.3,57.33 ; 73.71,100.51 TP4.1 ; TP4.1 73.71,102.73 ; TP4.1 75.93,100.51 ; TP4.1 75.93,102.73 ; 12.75,101.46 TP2.1 ; TP2.1 14.97,99.24 ; TP2.1 14.97,101.46 ; TP2.1 12.75,99.24 ; TP14.1 45.45,74.79 ; TP14.1 43.23,74.79 ; TP14.1 43.23,72.57 ; TP14.1 45.45,72.57 ; TP11.1 32.12,80.51 ; TP11.1 29.89,78.29 ; TP11.1 32.12,78.29 ; TP11.1 29.89,80.51 ; 24.18,90.35 TP8.1 ; TP8.1 26.4,92.57 ; TP8.1 24.18,92.57 ; TP8.1 26.4,90.35
  LY4-SIG w0.508: TP13.1 10.53,57.33 ; TP13.1 8.3,59.55 ; TP13.1 10.53,59.55 ; TP13.1 8.3,57.33 ; TP14.1 45.45,72.57 ; TP14.1 45.45,74.79 ; TP14.1 43.23,74.79 ; TP14.1 43.23,72.57 ; TP12.1 141.97,27.49 ; TP12.1 139.75,29.71 ; TP12.1 141.97,29.71 ; TP12.1 139.75,27.49 ; 73.71,100.51 TP4.1 ; TP4.1 75.93,102.73 ; TP4.1 75.93,100.51 ; TP4.1 73.71,102.73 ; 12.75,99.24 TP2.1 ; TP2.1 12.75,101.46 ; TP2.1 14.97,99.24 ; TP2.1 14.97,101.46 ; TP11.1 32.12,78.29 ; TP11.1 32.12,80.51 ; TP11.1 29.89,78.29 ; TP11.1 29.89,80.51 ; 2.59,68.13 TP7.1 ; TP7.1 2.59,70.35 ; TP7.1 4.81,70.35 ; TP7.1 4.81,68.13 ; TP8.1 26.4,92.57 ; TP8.1 24.18,90.35 ; TP8.1 24.18,92.57 ; TP8.1 26.4,90.35
  LY5-GND w0.508: TP8.1 26.4,92.57 ; TP8.1 26.4,90.35 ; TP8.1 24.18,90.35 ; TP8.1 24.18,92.57 ; TP12.1 141.97,27.49 ; TP12.1 139.75,27.49 ; TP12.1 139.75,29.71 ; TP12.1 141.97,29.71 ; TP13.1 10.53,57.33 ; TP13.1 8.3,57.33 ; TP13.1 10.53,59.55 ; TP13.1 8.3,59.55 ; TP4.1 75.93,102.73 ; TP4.1 75.93,100.51 ; TP4.1 73.71,100.51 ; TP4.1 73.71,102.73 ; 2.59,68.13 TP7.1 ; TP7.1 4.81,68.13 ; TP7.1 2.59,70.35 ; TP7.1 4.81,70.35 ; 29.89,78.29 TP11.1 ; TP11.1 29.89,80.51 ; TP11.1 32.12,80.51 ; TP11.1 32.12,78.29 ; 43.23,72.57 TP14.1 ; TP14.1 43.23,74.79 ; TP14.1 45.45,72.57 ; TP14.1 45.45,74.79 ; 12.75,99.24 TP2.1 ; TP2.1 12.75,101.46 ; TP2.1 14.97,99.24 ; TP2.1 14.97,101.46
  LY6-SIG w0.508: 12.75,101.46 TP2.1 ; TP2.1 14.97,99.24 ; TP2.1 12.75,99.24 ; TP2.1 14.97,101.46 ; TP13.1 10.53,59.55 ; TP13.1 8.3,59.55 ; TP13.1 10.53,57.33 ; TP13.1 8.3,57.33 ; 24.18,90.35 TP8.1 ; TP8.1 26.4,90.35 ; TP8.1 24.18,92.57 ; TP8.1 26.4,92.57 ; 43.23,74.79 TP14.1 ; TP14.1 45.45,74.79 ; TP14.1 43.23,72.57 ; TP14.1 45.45,72.57 ; 73.71,102.73 TP4.1 ; TP4.1 75.93,102.73 ; TP4.1 75.93,100.51 ; TP4.1 73.71,100.51 ; 29.89,80.51 TP11.1 ; TP11.1 32.12,78.29 ; TP11.1 29.89,78.29 ; TP11.1 32.12,80.51 ; 139.75,29.71 TP12.1 ; TP12.1 139.75,27.49 ; TP12.1 141.97,27.49 ; TP12.1 141.97,29.71 ; TP7.1 4.81,68.13 ; TP7.1 2.59,68.13 ; TP7.1 4.81,70.35 ; TP7.1 2.59,70.35
  LY7-GND w0.508: 43.23,74.79 TP14.1 ; TP14.1 45.45,72.57 ; TP14.1 43.23,72.57 ; TP14.1 45.45,74.79 ; 8.3,59.55 TP13.1 ; TP13.1 10.53,59.55 ; TP13.1 10.53,57.33 ; TP13.1 8.3,57.33 ; 24.18,90.35 TP8.1 ; TP8.1 26.4,90.35 ; TP8.1 26.4,92.57 ; TP8.1 24.18,92.57 ; TP12.1 141.97,27.49 ; TP12.1 141.97,29.71 ; TP12.1 139.75,29.71 ; TP12.1 139.75,27.49 ; 73.71,102.73 TP4.1 ; TP4.1 73.71,100.51 ; TP4.1 75.93,102.73 ; TP4.1 75.93,100.51 ; 2.59,70.35 TP7.1 ; TP7.1 4.81,68.13 ; TP7.1 4.81,70.35 ; TP7.1 2.59,68.13 ; 12.75,101.46 TP2.1 ; TP2.1 14.97,99.24 ; TP2.1 14.97,101.46 ; TP2.1 12.75,99.24 ; 29.89,80.51 TP11.1 ; TP11.1 29.89,78.29 ; TP11.1 32.12,78.29 ; TP11.1 32.12,80.51
  BOTTOM w0.203: v1(90.77,115.67) 90.36,116.08 90.33,116.08 90.19,116.22 J3.51 ; J2.24 v1(122.17,114.54) 121.67,115.04 J4.27 ; 86.01,115.12 86.36,115.47 J3.44 ; 86.01,115.12 85.74,114.86 85.74,114.25 v1(86.28,113.71) ; 86.01,115.12 85.86,115.28 J3.43 ; J4.23 119.68,115.09 v1(120.18,114.59) J2.28 ; J3.35 81.86,115.01 v1(82.36,114.51) J1.16 ; J3.47 87.86,114.62 v1(88.15,114.32) 88.36,114.53 J3.48 ; J4.10 v1(113.18,114.32) ; J4.35 125.67,115.01 v1(126.17,114.51) J2.16 ; v1(130.19,113.82) 129.56,114.45 129.56,114.86 129.82,115.12 ; J1.32 v1(74.36,114.55) 73.86,115.05 J3.19 ; J1.24 v1(78.36,114.54) 77.86,115.04 J3.27 ; J4.43 129.67,115.28 129.82,115.12 ; J3.31 79.86,115 v1(80.36,114.5) J1.20 ; 129.82,115.12 130.17,115.47 J4.44 ; J3.23 75.86,115.09 v1(76.36,114.59) J1.28 ; J2.20 v1(124.17,114.5) 123.67,115 J4.31 ; J4.47 131.67,114.62 v1(131.97,114.32) 132.17,114.53 J4.48 ; J3.40 84.36,114.9 v1(84.11,114.65) 83.86,114.9 J1.13 ; J1.39 v1(70.86,114.48) ; J3.10 v1(69.36,114.32) ; J2.32 v1(118.18,114.55) 117.68,115.05 J4.19 ; J1.36 v1(72.36,114.58) ; J2.39 v1(114.68,114.48) ; J2.13 127.67,115.12 127.8,114.98 v1(127.8,114.45) 128.17,114.82 J4.40 ; J2.36 v1(116.18,114.58) ; v1(134.64,115.16) 134.1,115.16 133.67,115.59 J4.51
  BOTTOM w0.381: v1(108.22,16.66) 107.6,16.66 R44.1 ; C18.1 14.74,88.25 v1(14.55,88.06) ; C46.1 v1(67.44,2.68)
  BOTTOM w0.508: U16.AJ19 v1(80.13,49.79) ; U16.C7 v1(62.35,16.77) ; v1(59.72,3.95) 59.33,3.55 59.33,3.33 58.84,2.84 C187.1 ; U16.AE7 v1(62.35,44.71) ; U16.AG29 v1(92.83,47.25) ; U16.F14 v1(71.24,20.58) ; U16.AL3 v1(57.27,52.33) ; U16.AG17 v1(77.59,47.25) ; U16.AK8 v1(63.62,51.06) ; J2.55 v1(113.67,122.78) ; U16.AF16 v1(73.78,45.98) ; U16.B28 v1(91.56,15.5) ; U16.E31 v1(95.37,19.31) ; U16.AJ7 v1(62.35,49.79) ; U16.J3 v1(57.27,24.39) ; U16.AE25 v1(87.75,44.71) ; U16.G13 v1(69.97,21.85) ; U16.AD2 v1(56,43.44) ; J1.53 v1(56.92,119.32) ; U16.G5 v1(59.81,21.85) ; U16.AK20 v1(81.4,51.06) ; U16.AK30 v1(94.1,51.06) ; U16.G25 v1(87.75,21.85) ; U16.AJ15 v1(72.51,49.79) ; J1.60 v1(95.76,121.6) ; U16.AJ13 v1(69.97,49.79) ; U16.H2 v1(56,23.12) ; U16.V2 v1(56,35.82) ; C195.1 v1(89.93,91.74) ; J2.58 v1(128.68,122.79) ; U16.U29 v1(92.83,34.55) ; U16.E3 v1(57.27,19.31) ; U16.B10 v1(66.16,15.5) ; C190.1 41.16,18.44 v1(40.91,18.69) ; U16.G21 v1(82.67,21.85) ; U16.G9 v1(64.89,21.85) ; U16.N3 v1(57.27,29.47) ; J1.56 v1(74.86,122.84) ; U16.C11 v1(67.43,16.77) ; U16.C3 v1(57.27,16.77) ; U16.AH28 v1(91.56,48.52) ; U16.B2 v1(56,15.5) ; J1.59 v1(89.86,122.8) ; U16.T30 v1(94.1,33.28) ; U16.AG23 v1(85.21,47.25) ; U16.AE11 v1(67.43,44.71) ; U16.AH22 v1(83.94,48.52) ; U16.G3 v1(57.27,21.85) ; C197.1 v1(69.61,100) ; U16.AF8 v1(63.62,45.98) ; U16.R29 v1(92.83,32.01) ; U16.C23 v1(85.21,16.77) ; U16.E9 v1(64.89,19.31) ; J2.59 v1(133.68,122.8) ; J2.60 v1(139.57,121.6) ; U16.C5 v1(59.81,16.77) ; U16.D30 v1(94.1,18.04) ; U16.J29 v1(92.83,24.39) ; U16.E25 v1(87.75,19.31) ; U16.AK12 v1(68.7,51.06) ; U16.C25 v1(87.75,16.77) ; U16.E19 v1(80.13,19.31) ; U16.E13 v1(69.97,19.31) ; U16.G19 v1(80.13,21.85) ; U16.AA3 v1(57.27,39.63) ; J1.58 v1(84.86,122.79) ; U16.AJ17 v1(77.59,49.79) ; U16.G7 v1(62.35,21.85) ; U16.AG11 v1(67.43,47.25) ; U16.AJ23 v1(85.21,49.79) ; J2.52 v1(105.67,114.56) ; U16.AC29 v1(92.83,42.17) ; U16.L29 v1(92.83,26.93) ; U16.AE21 v1(82.67,44.71) ; U16.AK16 v1(73.78,51.06) ; U16.D22 v1(83.94,18.04) ; U16.K30 v1(94.1,25.66) ; J2.53 v1(100.74,119.32) ; U16.C9 v1(64.89,16.77) ; U16.AJ3 v1(57.27,49.79) ; U16.AG3 v1(57.27,47.25) ; J1.55 v1(69.86,122.78) ; U16.AG13 v1(69.97,47.25) ; U16.Y2 v1(56,38.36) ; U16.AD20 v1(81.4,43.44) ; U16.AG21 v1(82.67,47.25) ; U16.W3 v1(57.27,37.09) ; J1.57 v1(81.58,121.32) ; U16.AG19 v1(80.13,47.25) ; U16.AG15 v1(72.51,47.25) ; U16.AE9 v1(64.89,44.71) ; J2.54 v1(108.67,122.84) ; U16.AJ9 v1(64.89,49.79) ; U16.E15 v1(72.51,19.31) ; J1.52 v1(61.86,114.56) ; U16.AJ25 v1(87.75,49.79) ; U16.AD6 v1(61.08,43.44) ; U16.E11 v1(67.43,19.31) ; v1(40.15,44.07) 40.28,44.19 40.28,44.6 40.78,45.11 C189.1 ; J2.57 v1(125.24,121.32) ; U16.D2 v1(56,18.04) ; U16.A1 v1(54.73,14.23) ; U16.G17 v1(77.59,21.85) ; U16.AH26 v1(89.02,48.52) ; U16.C15 v1(72.51,16.77) ; U16.R3 v1(57.27,32.01) ; U16.G23 v1(85.21,21.85) ; U16.AG27 v1(90.29,47.25) ; U16.H30 v1(94.1,23.12) ; J1.54 v1(64.86,122.84) ; U16.M2 v1(56,28.2) ; J2.61 v1(136.68,114.43) ; U16.AH2 v1(56,48.52) ; J1.61 v1(92.86,114.43) ; U16.W29 v1(92.83,37.09) ; U16.AK4 v1(58.54,51.06) ; U16.AK6 v1(61.08,51.06) ; U16.AK28 v1(91.56,51.06) ; U16.B30 v1(94.1,15.5) ; U16.AE17 v1(77.59,44.71) ; U16.U3 v1(57.27,34.55) ; U16.AG25 v1(87.75,47.25) ; U16.AJ27 v1(90.29,49.79) ; U16.AH4 v1(58.54,48.52) ; U16.E7 v1(62.35,19.31) ; U16.C17 v1(77.59,16.77) ; U16.M30 v1(94.1,28.2) ; U16.D28 v1(91.56,18.04) ; U16.C19 v1(80.13,16.77) ; U16.AH6 v1(61.08,48.52) ; J2.56 v1(118.67,122.84) ; U16.AC3 v1(57.27,42.17) ; U16.E21 v1(82.67,19.31) ; U16.M28 v1(91.56,28.2) ; U16.G27 v1(90.29,21.85) ; U16.G29 v1(92.83,21.85) ; U16.H6 v1(61.08,23.12) ; U16.AE29 v1(92.83,44.71) ; U16.AF14 v1(71.24,45.98)
  BOTTOM w0.635: C123.1 v1(73.04,72.54) ; v1(107.84,64.79) 108.6,64.03 C114.1 ; C87.1 v1(114.06,40.03) ; C117.1 v1(101.24,3.2) ; C116.1 v1(108.6,7.14) ; C119.1 v1(41.04,17.17) ; C89.1 v1(58.06,70.64) ; C121.1 v1(44.85,68.99) ; C88.1 v1(37.99,39.72) ; v1(91.58,70.89) 91.84,70.64 C113.1 ; C120.1 v1(38.24,60.98) ; C122.1 v1(38.24,27.33) ; C118.1 v1(38.24,50.57) ; 113.68,27.96 v1(113.68,30.12) ; C115.1 v1(111.14,48.67) ; C86.1 v1(43.58,7.9)
  vias: v1(0.97,122.89) v1(0.97,117.81) v1(0.97,115.27) v1(0.97,112.73) v1(0.97,110.19) v1(0.97,107.65) v1(0.97,105.11) v1(0.97,102.57) v1(0.97,100.03) v1(0.97,97.49) v1(0.97,94.95) v1(0.97,92.41) v1(0.97,89.87) v1(0.97,87.33) v1(0.97,84.79) v1(0.97,82.25) v1(0.97,79.71) v1(0.97,77.17) v1(0.97,74.63) v1(0.97,72.09) v1(0.97,69.55) v1(0.97,67.01) v1(0.97,64.47) v1(0.97,61.93) v1(0.97,59.39) v1(0.97,56.85) v1(0.97,54.31) v1(0.97,51.77) v1(0.97,49.23) v1(0.97,46.69) v1(0.97,44.15) v1(0.97,41.61) v1(0.97,39.07) v1(0.97,36.53) v1(0.97,33.99) v1(0.97,31.45) v1(0.97,28.91) v1(0.97,26.37) v1(0.97,23.83) v1(0.97,21.29) v1(0.97,18.75) v1(0.97,16.21) v1(0.97,13.67) v1(0.97,11.13) v1(0.97,9.22) v1(0.97,7.32) v1(0.97,2.87) v1(2.21,0.97) v1(2.36,124.03) v1(7.29,0.97) v1(7.44,124.03) v1(9.83,0.97) v1(9.98,124.03) v1(12.37,0.97) v1(12.52,124.03) v1(13.22,77.49) v1(13.22,76.22) v1(14.49,90.07) v1(14.49,77.49) v1(14.49,76.22) v1(14.49,73.68) v1(14.49,72.41) v1(14.91,0.97) v1(15.06,124.03) v1(17.45,0.97) v1(17.6,124.03) v1(19.99,0.97) v1(20.14,124.03) v1(22.53,0.97) v1(22.68,124.03) v1(25.07,0.97) v1(25.22,124.03) v1(27.61,0.97) v1(27.76,124.03) v1(30.15,0.97) v1(30.3,124.03) v1(32.69,0.97) v1(32.84,124.03) v1(35.23,0.97) v1(35.38,124.03) v1(37.77,0.97) v1(37.92,124.03) v1(40.31,0.97) v1(40.46,124.03) v1(42.85,0.97) v1(43,124.03) v1(45.39,0.97) v1(45.54,124.03) v1(47.93,0.97) v1(48.08,124.03) v1(50.47,0.97) v1(50.62,124.03) v1(53.01,0.97) v1(53.16,124.03) v1(55.55,0.97) v1(55.7,124.03) v1(58.09,0.97) v1(58.24,124.03) v1(60.63,0.97) v1(60.78,124.03) v1(63.17,0.97) v1(63.32,124.03) v1(65.71,0.97) v1(65.86,124.03) v1(68.25,0.97) v1(68.4,124.03) v1(70.79,0.97) v1(70.94,124.03) v1(73.33,0.97) v1(73.48,124.03) v1(75.87,0.97) v1(76.02,124.03) v1(78.41,0.97) v1(78.56,124.03) v1(80.95,0.97) v1(81.1,124.03) v1(83.49,0.97) v1(83.64,124.03) v1(86.03,0.97) v1(86.18,124.03) v1(88.57,0.97) v1(88.72,124.03) v1(91.11,0.97) v1(91.26,124.03) v1(93.65,0.97) v1(93.8,124.03) v1(96.19,0.97) v1(96.34,124.03) v1(98.73,0.97) v1(98.88,124.03) v1(101.27,0.97) v1(101.42,124.03) v1(103.81,0.97) v1(103.96,124.03) v1(106.35,0.97) v1(106.5,124.03) v1(108.89,0.97) v1(109.04,124.03) v1(111.43,0.97) v1(111.58,124.03) v1(113.97,0.97) v1(114.12,124.03) v1(116.51,0.97) v1(116.66,124.03) v1(119.05,0.97) v1(119.2,124.03) v1(121.59,0.97) v1(121.74,124.03) v1(124.13,0.97) v1(124.28,124.03) v1(126.67,0.97) v1(126.82,124.03) v1(129.21,0.97) v1(129.36,124.03) v1(131.75,0.97) v1(131.9,124.03) v1(134.29,0.97) v1(134.44,124.03) v1(136.83,0.97) v1(136.98,124.03) v1(139.37,0.97) v1(139.52,124.03) v1(140.64,0.97) v1(140.79,124.03) v1(142.55,0.97) v1(142.69,124.03) v1(146.99,0.97) v1(147.14,124.03) v1(149.03,123.39) v1(149.03,122.12) v1(149.03,118.31) v1(149.03,115.77) v1(149.03,113.23) v1(149.03,110.69) v1(149.03,108.15) v1(149.03,105.61) v1(149.03,103.07) v1(149.03,100.53) v1(149.03,97.99) v1(149.03,95.45) v1(149.03,92.91) v1(149.03,90.37) v1(149.03,87.83) v1(149.03,85.29) v1(149.03,82.75) v1(149.03,80.21) v1(149.03,77.67) v1(149.03,75.13) v1(149.03,72.59) v1(149.03,70.05) v1(149.03,67.51) v1(149.03,64.97) v1(149.03,62.43) v1(149.03,59.89) v1(149.03,57.35) v1(149.03,54.81) v1(149.03,52.27) v1(149.03,49.73) v1(149.03,47.19) v1(149.03,44.65) v1(149.03,42.11) v1(149.03,39.57) v1(149.03,37.03) v1(149.03,34.49) v1(149.03,31.95) v1(149.03,29.41) v1(149.03,26.87) v1(149.03,24.33) v1(149.03,21.79) v1(149.03,19.25) v1(149.03,16.71) v1(149.03,14.17) v1(149.03,11.63) v1(149.03,9.09) v1(149.03,7.18) v1(149.03,2.74) v1(149.03,1.47)
